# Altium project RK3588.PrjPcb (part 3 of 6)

## Sheet LAN9696.SchDoc
size A2; SheetNumber: 7; SheetTotal: 22
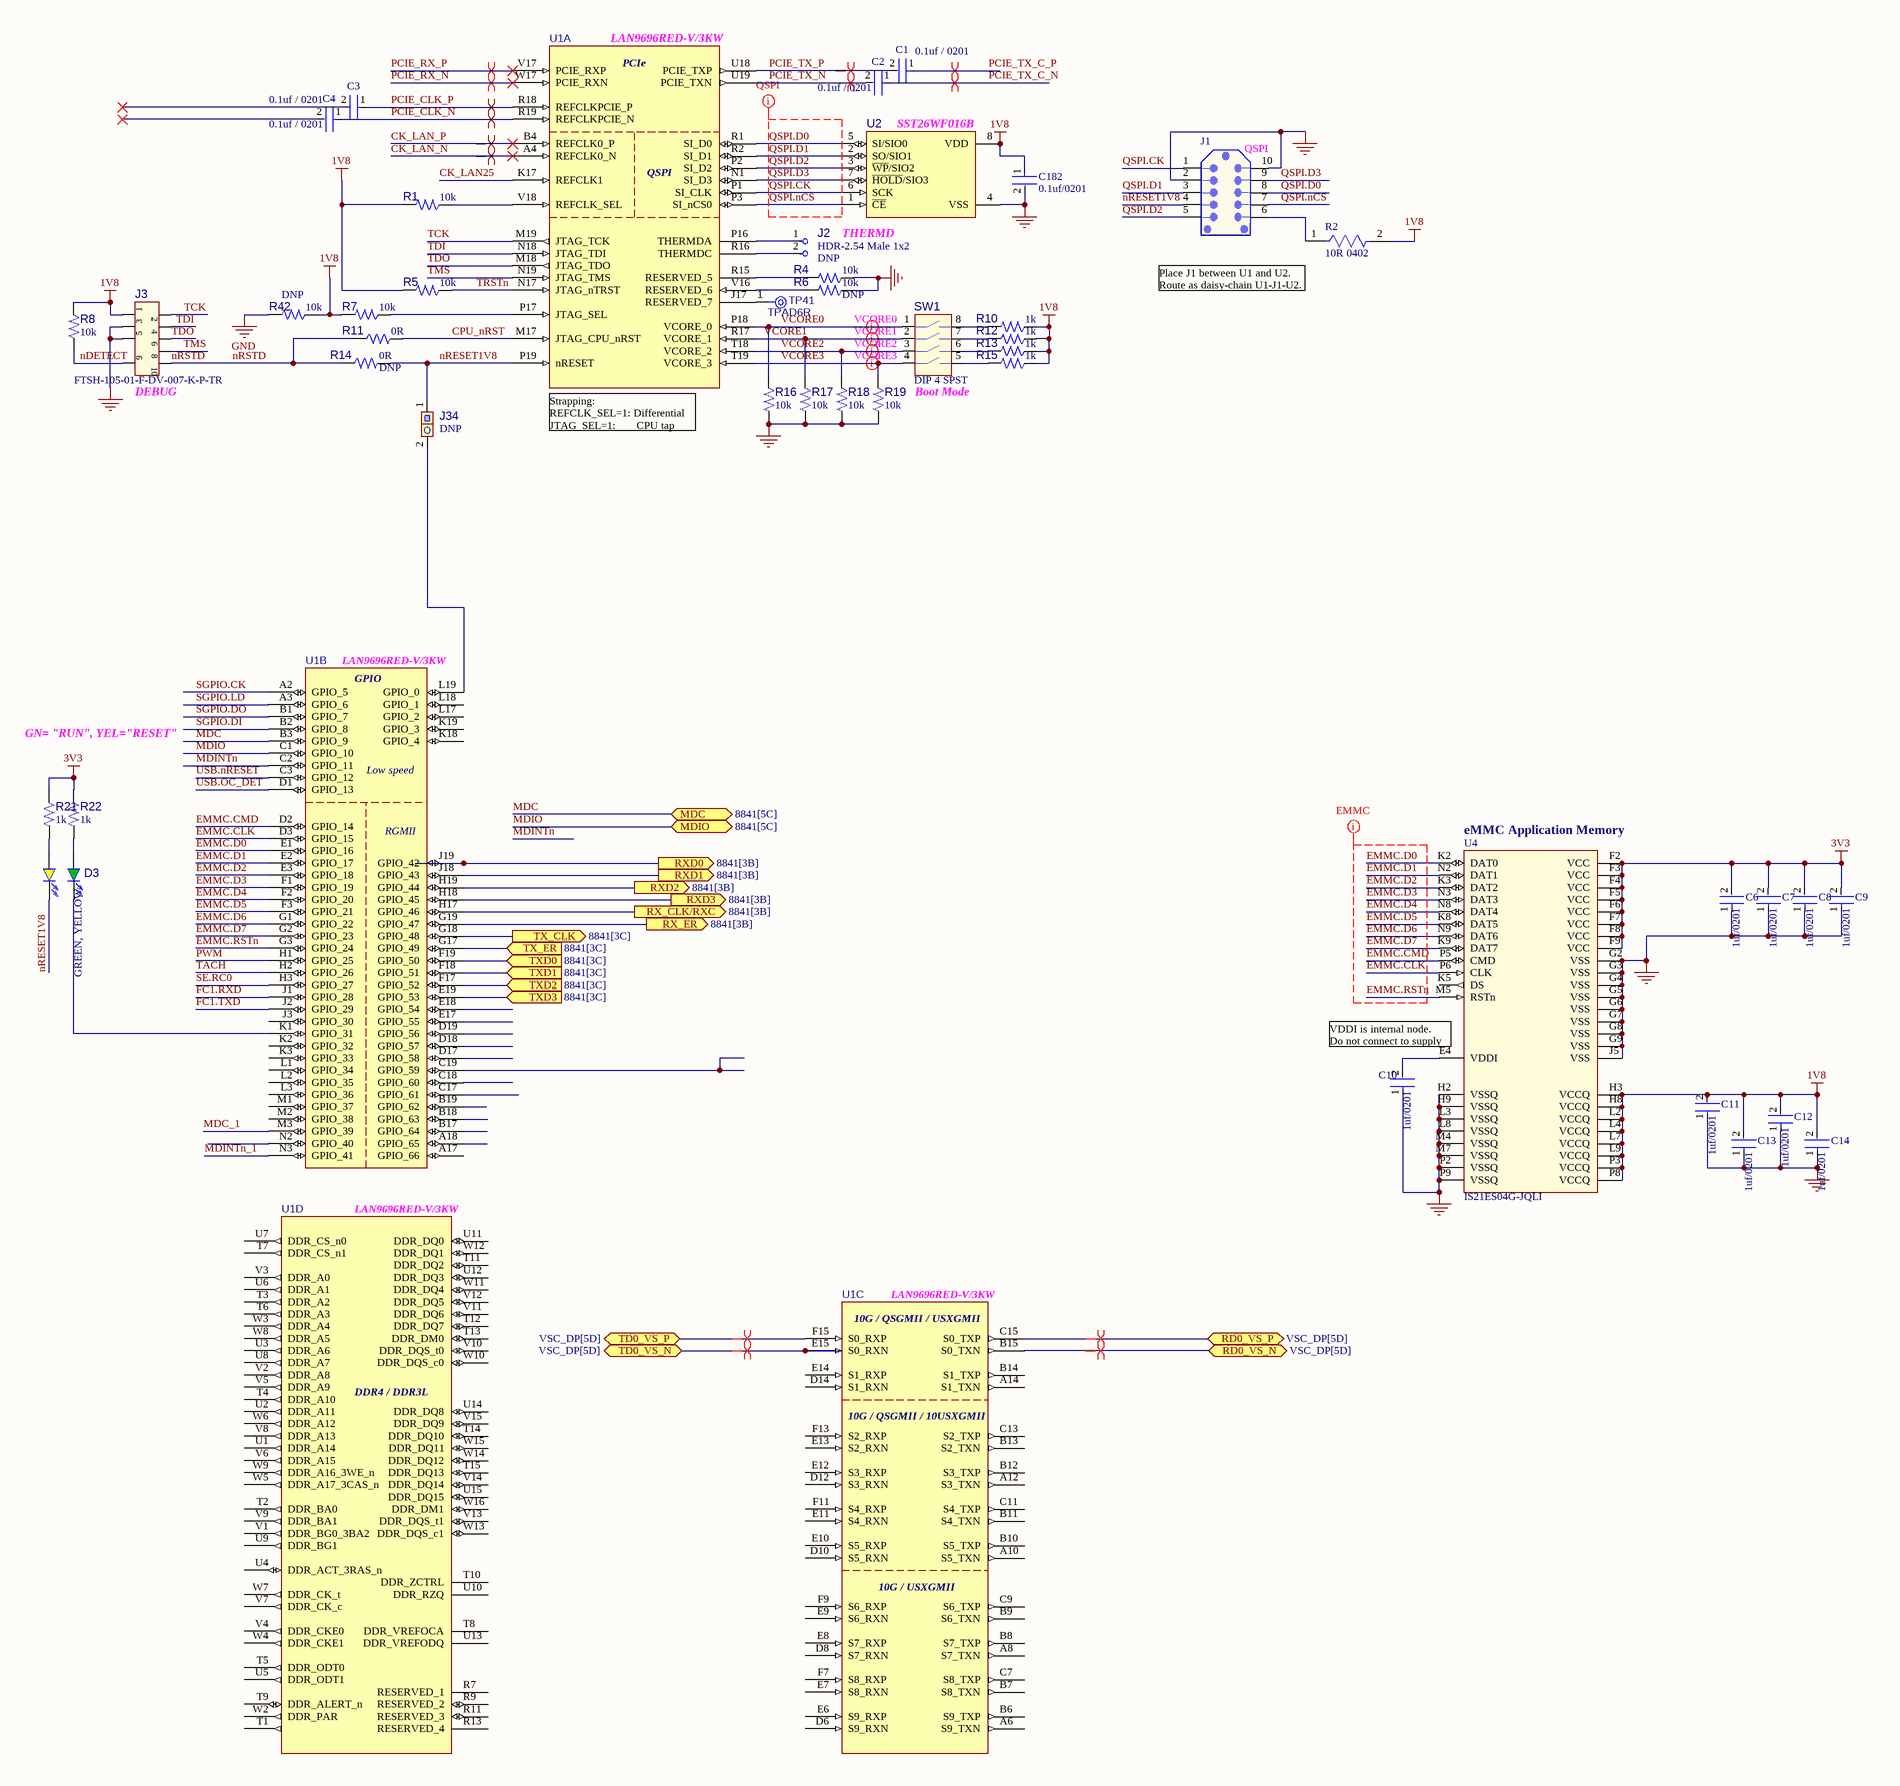
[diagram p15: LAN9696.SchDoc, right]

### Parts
C1  0.1uf / 0201  [FP-CC0201-BB-MFG]
C2  0.1uf / 0201  [FP-CC0201-BB-MFG]
C3  0.1uf / 0201  [FP-CC0201-BB-MFG]
C4  0.1uf / 0201  [FP-CC0201-BB-MFG]
C6  1uf/0201  [FP-CC0201-BA-MFG]
C7  1uf/0201  [FP-CC0201-BA-MFG]
C8  1uf/0201  [FP-CC0201-BA-MFG]
C9  1uf/0201  [FP-CC0201-BA-MFG]
C10  1uf/0201  [FP-CC0201-BA-MFG]
C11  1uf/0201  [FP-CC0201-BA-MFG]
C12  1uf/0201  [FP-CC0201-BA-MFG]
C13  1uf/0201  [FP-CC0201-BA-MFG]
C14  1uf/0201  [FP-CC0201-BA-MFG]
C182  0.1uf/0201  [FP-CC0201-BB-MFG]
D3  value GREEN, YELLOW  Legend Note: GN= "RUN", YEL="RESET"  [DIO_LED_DUAL_553-0123]  (hidden comment: LED_Dual_553-0123)
J1  Legend Note: QSPI  [CON_TAG TC2050 10P NO LEGS]  (hidden comment: CON-10P-TC2050-SMT-NO-LEGS)
J2  value HDR-2.54 Male 1x2  Populated: DNP  Legend Note: THERMD  [HDR_M_2.54_1x2]  (hidden comment: Header 1x2)
J3  value FTSH-105-01-F-DV-007-K-P-TR  Legend Note: DEBUG  [HDR_M_1.27_2x5_SMD_V_SAM_FTSH-105-01-F-DV-007-K]  (hidden comment: Header 2x5 POS 7 POLARIZED)
J34  Populated: DNP  [HDR_M_2.54_1x2]  (hidden comment: Header 1x2)
R1  value 10k  [RES_C_0402]  (hidden comment: Resistor)
R2  10R 0402  [FP-RT0402-MFG]
R4  value 10k  [RES_C_0402]  (hidden comment: Resistor)
R5  value 10k  [RES_C_0402]  (hidden comment: Resistor)
R6  value 10k  Populated: DNP  [RES_C_0402]  (hidden comment: Resistor)
R7  value 10k  [RES_C_0402]  (hidden comment: Resistor)
R8  value 10k  [RES_C_0402]  (hidden comment: Resistor)
R10  value 1k  [RES_C_0402]  (hidden comment: Resistor)
R11  value 0R  [RES_C_0402]  (hidden comment: Resistor)
R12  value 1k  [RES_C_0402]  (hidden comment: Resistor)
R13  value 1k  [RES_C_0402]  (hidden comment: Resistor)
R14  value 0R  Populated: DNP  [RES_C_0402]  (hidden comment: Resistor)
R15  value 1k  [RES_C_0402]  (hidden comment: Resistor)
R16  value 10k  [RES_C_0402]  (hidden comment: Resistor)
R17  value 10k  [RES_C_0402]  (hidden comment: Resistor)
R18  value 10k  [RES_C_0402]  (hidden comment: Resistor)
R19  value 10k  [RES_C_0402]  (hidden comment: Resistor)
R21  value 1k  [RES_C_0402]  (hidden comment: Resistor)
R22  value 1k  [RES_C_0402]  (hidden comment: Resistor)
R42  DNP  value 10k  [RES_C_0402]
SW1  value DIP 4 SPST  Legend Note: Boot Mode  [SW_SMD_1.27MM X 4 copal]  (hidden comment: Switch DIP 4 Pos)
TP41  TPAD6R  [TP06R]  (no BOM)
U1  LAN9696RED-V/3KW  [BGA-356_P0.8_17x17x1.68]  (parts A,B,C,D of 6)
U2  Legend Note: SST26WF016B  [SOIC-8]  (hidden comment: SST26WFXXX SOIC-8)
U4  value IS21ES04G-JQLI  [FBGA-100_14x18]  (hidden comment: eMMC MLC NAND flash 200MHz)

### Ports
MDC (bidir, see 8841[5C]), MDIO (bidir, see 8841[5C]), RD0_VS_N (bidir, see VSC_DP[5D]), RD0_VS_P (bidir, see VSC_DP[5D]), RX_CLK/RXC (out, see 8841[3B]), RX_ER (out, see 8841[3B]), RXD0 (out, see 8841[3B]), RXD1 (out, see 8841[3B]), RXD2 (out, see 8841[3B]), RXD3 (out, see 8841[3B]), TD0_VS_N (bidir, see VSC_DP[5D]), TD0_VS_P (bidir, see VSC_DP[5D]), TX_CLK (out, see 8841[3C]), TX_ER (in, see 8841[3C]), TXD0 (in, see 8841[3C]), TXD1 (in, see 8841[3C]), TXD2 (in, see 8841[3C]), TXD3 (in, see 8841[3C])

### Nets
1V8: C11.2 C12.2 C13.2 C14.2 C182.1 J3.1 R1.2 R2.2 R5.2 R7.2 R8.2 R10.1 R12.1 R13.1 R15.1 R42.1 U2.8(VDD) U4.H3(VCCQ) U4.H8(VCCQ) U4.L2(VCCQ) U4.L4(VCCQ) U4.L7(VCCQ) U4.L9(VCCQ) U4.P3(VCCQ) U4.P8(VCCQ)
3V3: C6.2 C7.2 C8.2 C9.2 R21.1 R22.1 U4.F2(VCC) U4.F3(VCC) U4.F4(VCC) U4.F5(VCC) U4.F6(VCC) U4.F7(VCC) U4.F8(VCC) U4.F9(VCC)
GND: C6.1 C7.1 C8.1 C9.1 C10.1 C11.1 C12.1 C13.1 C14.1 C182.2 J1.2 J1.10 J3.3 J3.5 R4.1 R6.1 R16.1 R17.1 R18.1 R19.1 R42.2 U2.4(VSS) U4.G2(VSS) U4.G3(VSS) U4.G4(VSS) U4.G5(VSS) U4.G6(VSS) U4.G7(VSS) U4.G8(VSS) U4.G9(VSS) U4.H2(VSSQ) U4.H9(VSSQ) U4.J5(VSS) U4.L3(VSSQ) U4.L8(VSSQ) U4.M4(VSSQ) U4.M7(VSSQ) U4.P2(VSSQ) U4.P9(VSSQ)
CK_LAN25: U1.K17(REFCLK1)
CK_LAN_N: U1.A4(REFCLK0_N)
CK_LAN_P: U1.B4(REFCLK0_P)
CLK125EN: U1.G19(GPIO_47) ; port RX_ER
CPU_nRST: R11.2 U1.M17(JTAG_CPU_nRST)
EMMC.CLK: U1.D3(GPIO_15) U4.P6(CLK)
EMMC.CMD: U1.D2(GPIO_14) U4.P5(CMD)
EMMC.D0: U1.E1(GPIO_16) U4.K2(DAT0)
EMMC.D1: U1.E2(GPIO_17) U4.N2(DAT1)
EMMC.D2: U1.E3(GPIO_18) U4.K3(DAT2)
EMMC.D3: U1.F1(GPIO_19) U4.N3(DAT3)
EMMC.D4: U1.F2(GPIO_20) U4.N8(DAT4)
EMMC.D5: U1.F3(GPIO_21) U4.K8(DAT5)
EMMC.D6: U1.G1(GPIO_22) U4.N9(DAT6)
EMMC.D7: U1.G2(GPIO_23) U4.K9(DAT7)
EMMC.RSTn: U1.G3(GPIO_24) U4.M5(RSTn)
FC1.RXD: U1.J1(GPIO_28)
FC1.TXD: U1.J2(GPIO_29)
MDC: U1.B3(GPIO_9) ; port MDC
MDC_1: U1.M3(GPIO_39)
MDINTn: U1.C2(GPIO_11)
MDINTn_1: U1.N3(GPIO_41)
MDIO: U1.C1(GPIO_10) ; port MDIO
MODE0: U1.J19(GPIO_42) ; port RXD0
MODE1: U1.J18(GPIO_43) ; port RXD1
MODE2: U1.H19(GPIO_44) ; port RXD2
MODE3: U1.H18(GPIO_45) ; port RXD3
MODE4: U1.H17(GPIO_46) ; port RX_CLK/RXC
nDETECT: J3.9 R8.1
nRESET1V8: D3.1 J1.4 J34.1 R14.2 U1.P19(nRESET)
nRSTD: J3.10 R11.1 R14.1
PCIE_CLK_N: C4.1 U1.R19(REFCLKPCIE_N)
PCIE_CLK_P: C3.1 U1.R18(REFCLKPCIE_P)
PCIE_RX_N: U1.W17(PCIE_RXN)
PCIE_RX_P: U1.V17(PCIE_RXP)
PCIE_TX_C_N: C2.1
PCIE_TX_C_P: C1.1
PCIE_TX_N: C2.2 U1.U19(PCIE_TXN)
PCIE_TX_P: C1.2 U1.U18(PCIE_TXP)
PWM: U1.H1(GPIO_25)
QSPI.CK: J1.1 U1.P1(SI_CLK) U2.6(SCK)
QSPI.D0: J1.8 U1.R1(SI_D0) U2.5(SI/SIO0)
QSPI.D1: J1.3 U1.R2(SI_D1) U2.2(SO/SIO1)
QSPI.D2: J1.5 U1.P2(SI_D2) U2.3(~{WP}/SIO2)
QSPI.D3: J1.9 U1.N1(SI_D3) U2.7(~{HOLD}/SIO3)
QSPI.nCS: J1.7 U1.P3(SI_nCS0) U2.1(~{CE})
RD0_VS_N: U1.B15(S0_TXN) ; port RD0_VS_N
RD0_VS_P: U1.C15(S0_TXP) ; port RD0_VS_P
SE.RC0: U1.H3(GPIO_27)
SGPIO.CK: U1.A2(GPIO_5)
SGPIO.DI: U1.B2(GPIO_8)
SGPIO.DO: U1.B1(GPIO_7)
SGPIO.LD: U1.A3(GPIO_6)
TACH: U1.H2(GPIO_26)
TCK: J3.2 U1.M19(JTAG_TCK)
TD0_VS_N: U1.E15(S0_RXN) ; port TD0_VS_N
TD0_VS_P: U1.F15(S0_RXP) ; port TD0_VS_P
TDI: J3.4 U1.N18(JTAG_TDI)
TDO: J3.6 U1.M18(JTAG_TDO)
TMS: J3.8 U1.N19(JTAG_TMS)
TRSTn: R5.1 U1.N17(JTAG_nTRST)
TX_CLK: U1.G18(GPIO_48) ; port TX_CLK
TX_ER: U1.G17(GPIO_49) ; port TX_ER
TXD0: U1.F19(GPIO_50) ; port TXD0
TXD1: U1.F18(GPIO_51) ; port TXD1
TXD2: U1.F17(GPIO_52) ; port TXD2
TXD3: U1.E19(GPIO_53) ; port TXD3
USB.nRESET: U1.C3(GPIO_12)
USB.OC_DET: U1.D1(GPIO_13)
VCORE0: R16.2 SW1.1 U1.P18(VCORE_0)
VCORE1: R17.2 SW1.2 U1.R17(VCORE_1)
VCORE2: R18.2 SW1.3 U1.T18(VCORE_2)
VCORE3: R19.2 SW1.4 U1.T19(VCORE_3)
NetC10_2: C10.2 U4.E4(VDDI)
NetD3_2: D3.2 R21.2
NetD3_3: D3.3 U1.K1(GPIO_31)
NetD3_4: D3.4 R22.2
NetJ1_6: J1.6 R2.1
NetJ2_1: J2.1 U1.P16(THERMDA)
NetJ2_2: J2.2 U1.R16(THERMDC)
NetJ34_2: J34.2 U1.L19(GPIO_0)
NetR1_1: R1.1 U1.V18(REFCLK_SEL)
NetR4_2: R4.2 U1.R15(RESERVED_5)
NetR6_2: R6.2 U1.V16(RESERVED_6)
NetR7_1: R7.1 U1.P17(JTAG_SEL)
NetR10_2: R10.2 SW1.8
NetR12_2: R12.2 SW1.7
NetR13_2: R13.2 SW1.6
NetR15_2: R15.2 SW1.5
NetTP41_1: TP41.1(TP) U1.J17(RESERVED_7)

Not connected (* = marked no-connect by the designer): C3 2*; C4 2*; U1 A6(S9_TXN) A8(S7_TXN) A10(S5_TXN) A12(S3_TXN) A14(S1_TXN) A17(GPIO_66) A18(GPIO_65) B6(S9_TXP) B7(S8_TXN) B8(S7_TXP) B9(S6_TXN) B10(S5_TXP) B11(S4_TXN) B12(S3_TXP) B13(S2_TXN) B14(S1_TXP) B17(GPIO_64) B18(GPIO_63) B19(GPIO_62) C7(S8_TXP) C9(S6_TXP) C11(S4_TXP) C13(S2_TXP) C17(GPIO_61) C18(GPIO_60) C19(GPIO_59) D6(S9_RXN) D8(S7_RXN) D10(S5_RXN) D12(S3_RXN) D14(S1_RXN) D17(GPIO_58) D18(GPIO_57) D19(GPIO_56) E6(S9_RXP) E7(S8_RXN) E8(S7_RXP) E9(S6_RXN) E10(S5_RXP) E11(S4_RXN) E12(S3_RXP) E13(S2_RXN) E14(S1_RXP) E17(GPIO_55) E18(GPIO_54) F7(S8_RXP) F9(S6_RXP) F11(S4_RXP) F13(S2_RXP) J3(GPIO_30) K2(GPIO_32) K3(GPIO_33) K18(GPIO_4) K19(GPIO_3) L1(GPIO_34) L2(GPIO_35) L3(GPIO_36) L17(GPIO_2) L18(GPIO_1) M1(GPIO_37) M2(GPIO_38) N2(GPIO_40) R7(RESERVED_1) R9(RESERVED_2) R11(RESERVED_3) R13(RESERVED_4) T1 T2(DDR_BA0) T3(DDR_A2) T4(DDR_A10) T5(DDR_ODT0) T6(DDR_A3) T7(DDR_CS_n1) T8(DDR_VREFOCA) T9(DDR_ALERT_n) T10(DDR_ZCTRL) T11(DDR_DQ2) T12(DDR_DQ7) T13(DDR_DM0) T14(DDR_DQ10) T15(DDR_DQ13) U1(DDR_A14) U2(DDR_A11) U3(DDR_A6) U4(DDR_ACT_3RAS_n) U5(DDR_ODT1) U6(DDR_A1) U7(DDR_CS_n0) U8(DDR_A7) U9(DDR_BG1) U10(DDR_RZQ) U11(DDR_DQ0) U12(DDR_DQ3) U13(DDR_VREFODQ) U14(DDR_DQ8) U15(DDR_DQ15) V1(DDR_BG0_3BA2) V2(DDR_A8) V3(DDR_A0) V4(DDR_CKE0) V5(DDR_A9) V6(DDR_A15) V7(DDR_CK_c) V8(DDR_A13) V9(DDR_BA1) V10(DDR_DQS_t0) V11(DDR_DQ6) V12(DDR_DQ5) V13(DDR_DQS_t1) V14(DDR_DQ14) V15(DDR_DQ9) W2(DDR_PAR) W3(DDR_A4) W4(DDR_CKE1) W5(DDR_A17_3CAS_n) W6(DDR_A12) W7(DDR_CK_t) W8(DDR_A5) W9(DDR_A16_3WE_n) W10(DDR_DQS_c0) W11(DDR_DQ4) W12(DDR_DQ1) W13(DDR_DQS_c1) W14(DDR_DQ12) W15(DDR_DQ11) W16(DDR_DM1); U4 K5(DS)

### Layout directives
rule Impedance Constraint [Min = 47.00    Max = 53.00    ]; net class QSPI; rule Routing Topology [Topology - Daisy-Simple]; rule Matched Net Lengths [Tolerance = 100mil]: QSPI.CK, QSPI.D0, QSPI.D1, QSPI.D2, QSPI.D3, QSPI.nCS
Legend Note: VCORE3: VCORE3
Legend Note: VCORE2: VCORE2
Legend Note: VCORE1: VCORE1
Legend Note: VCORE0: VCORE0
differential pair; rule Impedance Constraint [Min = 95.00    Max = 105.0    ]; rule Maximum Via Count Constraint [Max Count = 0]; net class HiSpeed; differential pair class PCIe; rule Matched Net Lengths [Tolerance = 5mil]: PCIE_RX_N, PCIE_RX_P, PCIE_TX_C_N, PCIE_TX_C_P
differential pair; rule Impedance Constraint [Min = 95.00    Max = 105.0    ]; rule Maximum Via Count Constraint [Max Count = 2]; differential pair class Clock; net class HiSpeed; rule Matched Net Lengths [Tolerance = 40mil]: CK_LAN_N, CK_LAN_P, PCIE_CLK_N, PCIE_CLK_P
differential pair; rule Impedance Constraint [Min = 95.00    Max = 105.0    ]; rule Maximum Via Count Constraint [Max Count = 0]; net class HiSpeed; differential pair class PCIe: PCIE_TX_N, PCIE_TX_P
rule Impedance Constraint [Min = 47.00    Max = 53.00    ]; net class EMMC_9696; rule Routing Topology [Topology - Daisy-Simple]; rule Matched Net Lengths [Tolerance = 100mil]: EMMC.CLK, EMMC.CMD, EMMC.D0, EMMC.D1, EMMC.D2, EMMC.D3, EMMC.D4, EMMC.D5, EMMC.D6, EMMC.D7, EMMC.RSTn
differential pair; net class 100Ohm: RD0_VS_N, RD0_VS_P, TD0_VS_N, TD0_VS_P

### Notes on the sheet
- Place J1 between U1 and U2.
  Route as daisy-chain U1-J1-U2.
- (near U1) Strapping:
  REFCLK_SEL=1: Differential
  JTAG_SEL=1:       CPU tap
- (near U4) eMMC Application Memory
- (near U4) VDDI is internal node.
  Do not connect to supply

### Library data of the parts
C1-C4 C182 = CMP-03422-001280-2: CAP CER 0.1UF 25V X5R 0201
C6-C14 = CMP-03422-000660-2: 1uF 6.3V X5R ±20% 0201 Multilayer Ceramic Capacitors MLCC - SMD/SMT ROHS; Manufacturer: Yageo; Manufacturer Part Number: CC0201MRX5R5BB105; Tolerance: 0.2; Temperature Coefficient: 15%; MN: CL03A105MQ3CSNH
D3 = DIODE1400: Manufacturer 1: Dialight; Manufacturer Part Number 1: 5530123F; Description_: DIO LED BI GREEN, YELLOW 2.0V 10mA TH 553-0XXX; Dev Tools Status: Design; Type: LED Bicolor; Forward Current: 10mA; Owner: Sam Charles; Populated: YES; Restricted Sourcing: No
J1 = CON1734: CON TAG 10P TC2050 SMT; Manufacturer 1: Tag-Connect LLC; Manufacturer Part Number 1: TC2050-IDC-NL; Dev Tools Status: Design; Owner: Jesus Aviles; Populated: DNP; Restricted Sourcing: No
J2 = CON1108: Manufacturer 1: FCI; Manufacturer Part Number 1: 68000-202HLF; Manufacturer 10: Shanghai NS-TECH; Manufacturer Part Number 10: NS-201-SH0100-1*2; Description_: CON HDR-2.54 Male 1x2 Gold 5.84MH TH VERT; Dev Tools Status: Production; Owner: Bogdan P (M91398); Restricted Sourcing: No
J3 = CON2256: Manufacturer 1: Samtec Inc.; Description_: CON HDR-1.27 MALE 2x5 Missing Pin 7 Polarized SMD VERT; Dev Tools Status: Production; Owner: Manikandan Balakrishnan; Populated: YES; Current: 3.4A per Contact; Restricted Sourcing: No
J34 = CON1108: Manufacturer 1: FCI; Manufacturer Part Number 1: 68000-202HLF; Manufacturer 10: Shanghai NS-TECH; Manufacturer Part Number 10: NS-201-SH0100-1*2; Value: HDR-2.54 Male 1x2; Description_: CON HDR-2.54 Male 1x2 Gold 5.84MH TH VERT; Dev Tools Status: Production; Owner: Bogdan P (M91398); Restricted Sourcing: No
R1 R4 R5 R7 R8 R16-R19 R42 = RSMT1019: Manufacturer 1: Panasonic; Manufacturer Part Number 1: ERJ-2RKF1002X; Tolerance: 1%; Description_: RES TKF 10k 1% 1/10W SMD 0402; Dev Tools Status: Production; Temperature Coeffcient: 100ppm/C; Power: 1/10W; Populated: Yes; Voltage: 50V; Owner: Brent Lanphear
R2 = CMP-2002-02548-2: RES SMD 10 OHM 1% 1/16W 0402; Manufacturer Part Number: RT0402FRE0710RL; Manufacturer: Yageo; Resistance: 10Ω; Voltage Rating: 50V; Tolerance: 0.01; Power Rating: 0.063W; Temperature Coefficient: 50 ppm/°C; Value: 10Ω
R6 = RSMT1019: Manufacturer 1: Panasonic; Manufacturer Part Number 1: ERJ-2RKF1002X; Tolerance: 1%; Description_: RES TKF 10k 1% 1/10W SMD 0402; Dev Tools Status: Production; Temperature Coeffcient: 100ppm/C; Power: 1/10W; Voltage: 50V; Owner: Brent Lanphear
R10 R12 R13 R15 R21 R22 = RES1022: Manufacturer 1: Panasonic; Manufacturer Part Number 1: ERJ-2RKF1001X; Tolerance: 1%; Description_: RES TKF 1k 1% 1/10W SMD 0402; Dev Tools Status: Production; Voltage: 50V; Power: 1/10W; Populated: YES; Owner: Tad Ahlvers; Temperature Coefficient: 100ppm/C
R11 = RSMT1040: Manufacturer 1: Yageo; Manufacturer Part Number 1: RC0402JR-070RL; Description_: RES TKF 0R 1/16W SMD 0402; Dev Tools Status: Production; Populated: Yes; Power: 1/16W; Owner: Sompoch Loboonlert
R14 = RSMT1040: Manufacturer 1: Yageo; Manufacturer Part Number 1: RC0402JR-070RL; Description_: RES TKF 0R 1/16W SMD 0402; Dev Tools Status: Production; Power: 1/16W; Owner: Sompoch Loboonlert
SW1 = SWITCH1051: Switch DIP; Manufacturer 1: Copal Electronics; Manufacturer Part Number 1: CHS-04TB; Description_: SWITCH DIP 4-POS SLIDE SMD 6V; Dev Tools Status: Production; Populated: YES
TP41 = CMP-00028-00002-2: 0.6mm round
U1 = MIC9729: Manufacturer 1: Microchip Technology; Description_: MCHP INTERFACE Industrial ETH SWITCH LAN9694 BGA356; Symbol: LAN969X BGA-356; Dev Tools Status: Design; Owner: Manikandan Balakrishnan; Populated: YES; Restricted Sourcing: No
U2 = MIC9680: Manufacturer 1: Microchip Technology; Manufacturer Part Number 1: SST26WF016BT-104I/SN; Value: SST26WF016; Description_: MCHP MEMORY SERIAL FLASH 16M 104MHz SST26WF016 SOIC-8; Dev Tools Status: Design; Owner: Sam Charles; Populated: YES; Restricted Sourcing: No
U4 = IC1641: Manufacturer 1: Flexxon; Manufacturer Part Number 1: FEMC004GTTE7-T13-17; MCHP-ID: IC1641; Description_: IC MEMORY IS21ES04G 32Gb eMMC FBGA-100; Dev Tools Status: Production; Vin: 3.3V; Owner: Ilie Galan; Populated: YES; Restricted Sourcing: No

## Sheet LAN9696_Supply.SchDoc
size A3; SheetNumber: 8; SheetTotal: 22
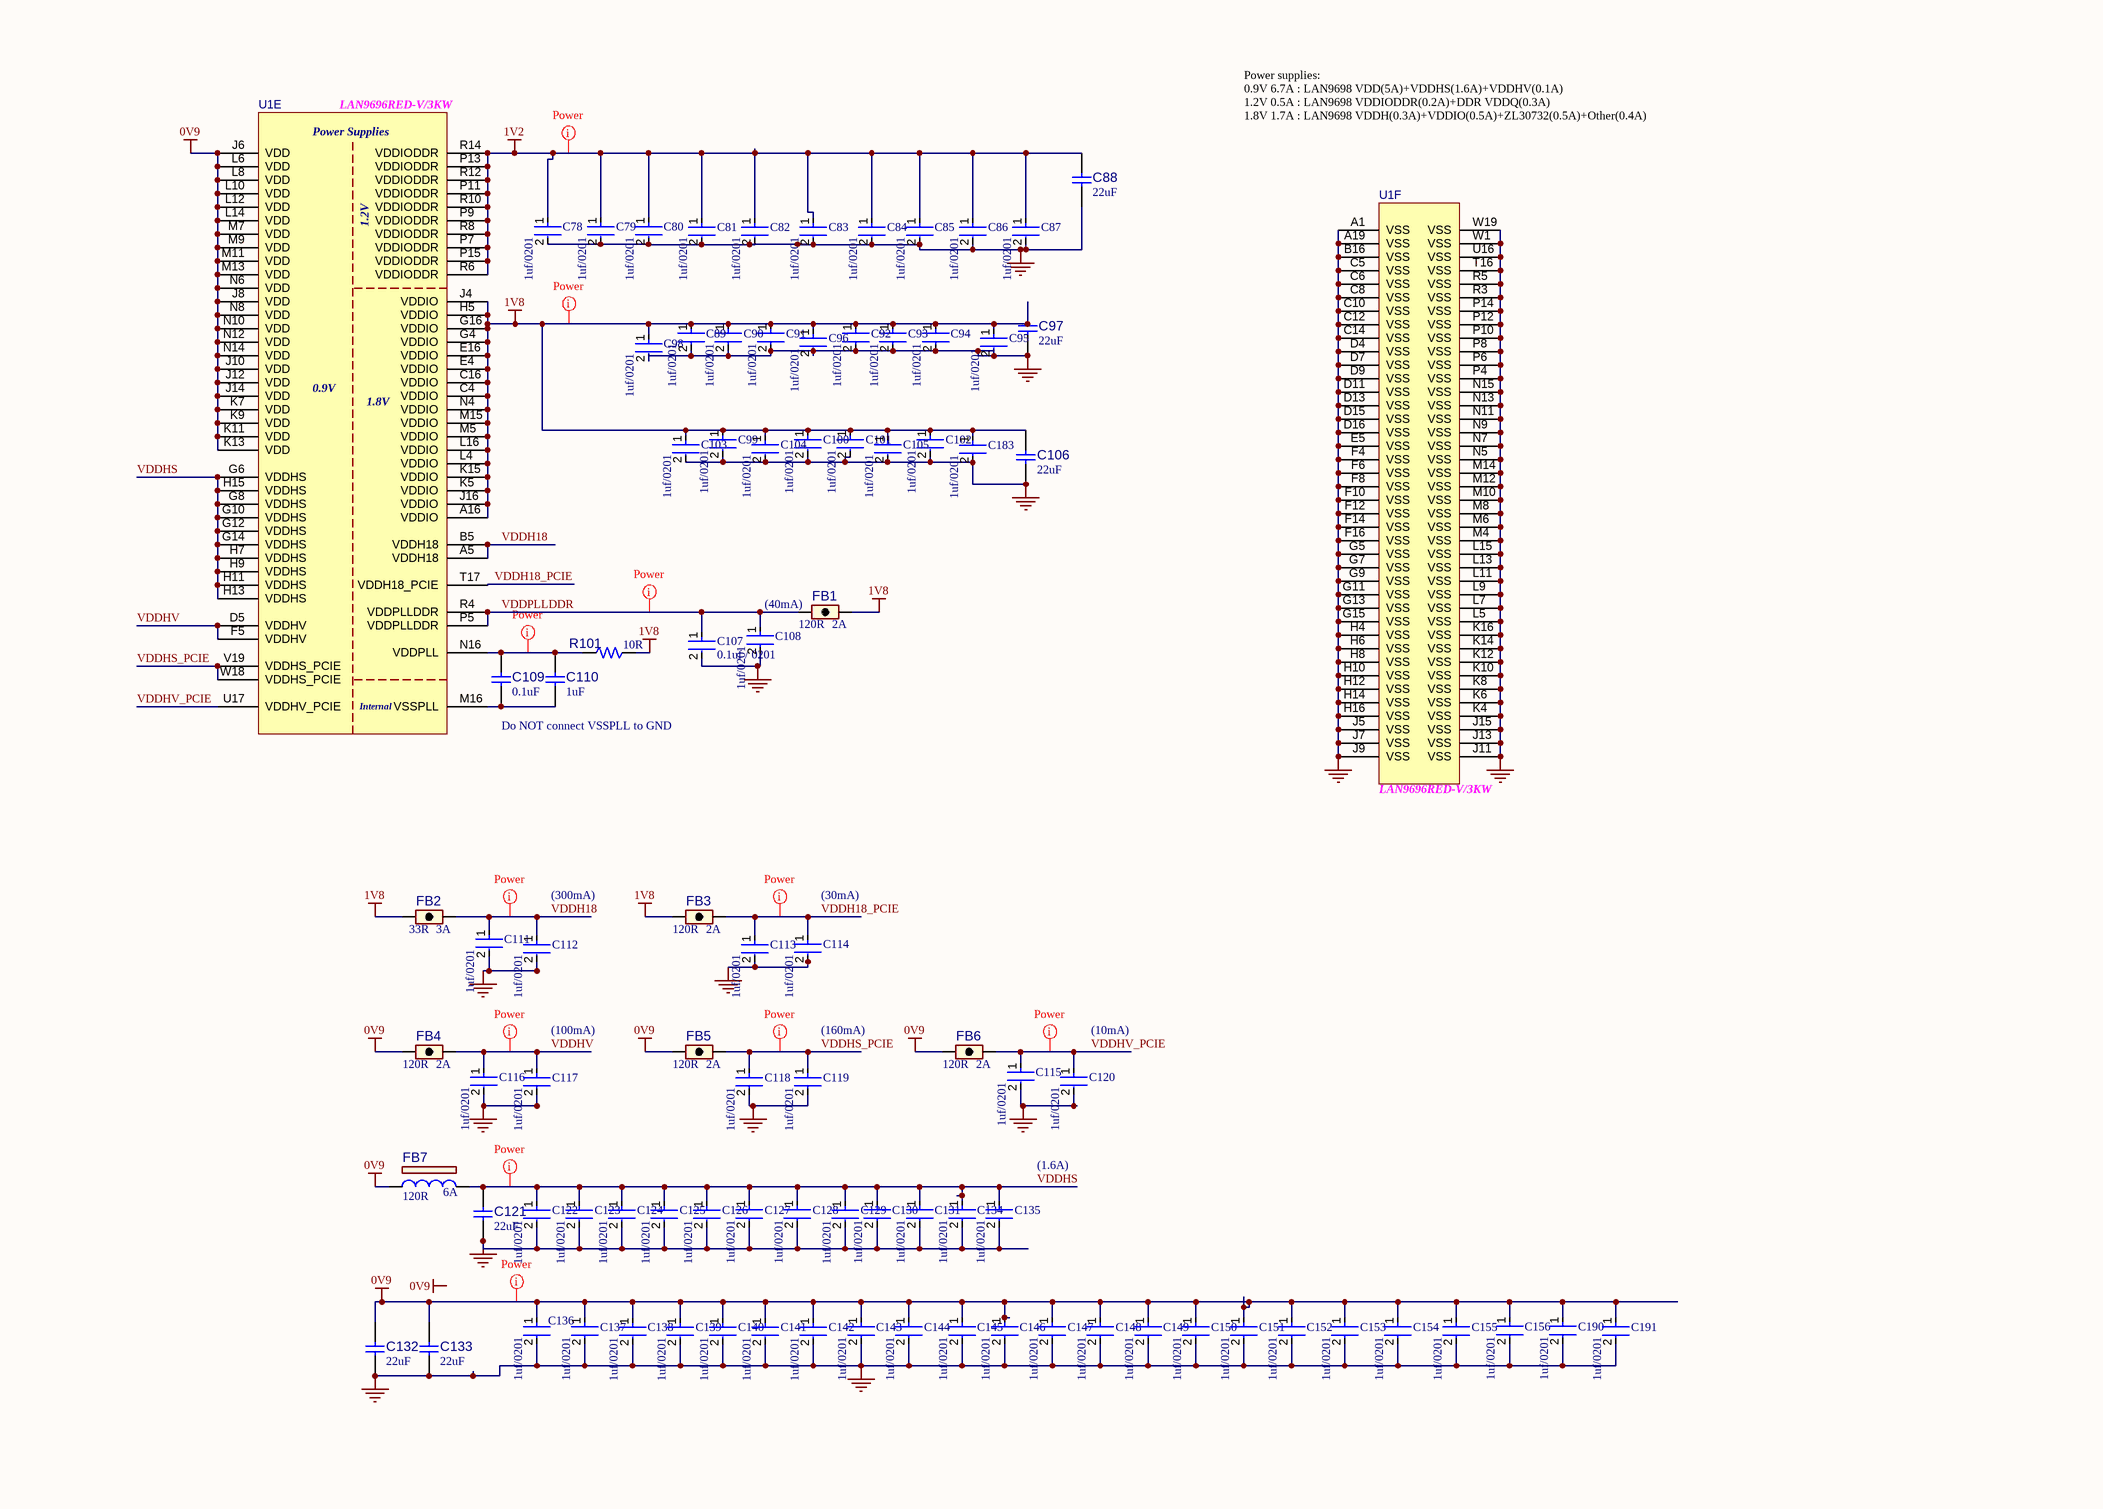
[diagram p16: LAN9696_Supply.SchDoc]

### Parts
C78  1uf/0201  [FP-CC0201-BA-MFG]
C79  1uf/0201  [FP-CC0201-BA-MFG]
C80  1uf/0201  [FP-CC0201-BA-MFG]
C81  1uf/0201  [FP-CC0201-BA-MFG]
C82  1uf/0201  [FP-CC0201-BA-MFG]
C83  1uf/0201  [FP-CC0201-BA-MFG]
C84  1uf/0201  [FP-CC0201-BA-MFG]
C85  1uf/0201  [FP-CC0201-BA-MFG]
C86  1uf/0201  [FP-CC0201-BA-MFG]
C87  1uf/0201  [FP-CC0201-BA-MFG]
C88  value 22uF  [CAP_C_0603]  (hidden comment: Capacitor NP)
C89  1uf/0201  [FP-CC0201-BA-MFG]
C90  1uf/0201  [FP-CC0201-BA-MFG]
C91  1uf/0201  [FP-CC0201-BA-MFG]
C92  1uf/0201  [FP-CC0201-BA-MFG]
C93  1uf/0201  [FP-CC0201-BA-MFG]
C94  1uf/0201  [FP-CC0201-BA-MFG]
C95  1uf/0201  [FP-CC0201-BA-MFG]
C96  1uf/0201  [FP-CC0201-BA-MFG]
C97  value 22uF  [CAP_C_0603]  (hidden comment: Capacitor NP)
C98  1uf/0201  [FP-CC0201-BA-MFG]
C99  1uf/0201  [FP-CC0201-BA-MFG]
C100  1uf/0201  [FP-CC0201-BA-MFG]
C101  1uf/0201  [FP-CC0201-BA-MFG]
C102  1uf/0201  [FP-CC0201-BA-MFG]
C103  1uf/0201  [FP-CC0201-BA-MFG]
C104  1uf/0201  [FP-CC0201-BA-MFG]
C105  1uf/0201  [FP-CC0201-BA-MFG]
C106  value 22uF  [CAP_C_0603]  (hidden comment: Capacitor NP)
C107  0.1uf / 0201  [FP-CC0201-BB-MFG]
C108  1uf/0201  [FP-CC0201-BA-MFG]
C109  value 0.1uF  [CAP_C_0201]  (hidden comment: Capacitor NP)
C110  value 1uF  [CAP_C_0201]  (hidden comment: Capacitor NP)
C111  1uf/0201  [FP-CC0201-BA-MFG]
C112  1uf/0201  [FP-CC0201-BA-MFG]
C113  1uf/0201  [FP-CC0201-BA-MFG]
C114  1uf/0201  [FP-CC0201-BA-MFG]
C115  1uf/0201  [FP-CC0201-BA-MFG]
C116  1uf/0201  [FP-CC0201-BA-MFG]
C117  1uf/0201  [FP-CC0201-BA-MFG]
C118  1uf/0201  [FP-CC0201-BA-MFG]
C119  1uf/0201  [FP-CC0201-BA-MFG]
C120  1uf/0201  [FP-CC0201-BA-MFG]
C121  value 22uF  [CAP_C_0603]  (hidden comment: Capacitor NP)
C122  1uf/0201  [FP-CC0201-BA-MFG]
C123  1uf/0201  [FP-CC0201-BA-MFG]
C124  1uf/0201  [FP-CC0201-BA-MFG]
C125  1uf/0201  [FP-CC0201-BA-MFG]
C126  1uf/0201  [FP-CC0201-BA-MFG]
C127  1uf/0201  [FP-CC0201-BA-MFG]
C128  1uf/0201  [FP-CC0201-BA-MFG]
C129  1uf/0201  [FP-CC0201-BA-MFG]
C130  1uf/0201  [FP-CC0201-BA-MFG]
C131  1uf/0201  [FP-CC0201-BA-MFG]
C132  value 22uF  [CAP_C_0603]  (hidden comment: Capacitor NP)
C133  value 22uF  [CAP_C_0603]  (hidden comment: Capacitor NP)
C134  1uf/0201  [FP-CC0201-BA-MFG]
C135  1uf/0201  [FP-CC0201-BA-MFG]
C136  1uf/0201  [FP-CC0201-BA-MFG]
C137  1uf/0201  [FP-CC0201-BA-MFG]
C138  1uf/0201  [FP-CC0201-BA-MFG]
C139  1uf/0201  [FP-CC0201-BA-MFG]
C140  1uf/0201  [FP-CC0201-BA-MFG]
C141  1uf/0201  [FP-CC0201-BA-MFG]
C142  1uf/0201  [FP-CC0201-BA-MFG]
C143  1uf/0201  [FP-CC0201-BA-MFG]
C144  1uf/0201  [FP-CC0201-BA-MFG]
C145  1uf/0201  [FP-CC0201-BA-MFG]
C146  1uf/0201  [FP-CC0201-BA-MFG]
C147  1uf/0201  [FP-CC0201-BA-MFG]
C148  1uf/0201  [FP-CC0201-BA-MFG]
C149  1uf/0201  [FP-CC0201-BA-MFG]
C150  1uf/0201  [FP-CC0201-BA-MFG]
C151  1uf/0201  [FP-CC0201-BA-MFG]
C152  1uf/0201  [FP-CC0201-BA-MFG]
C153  1uf/0201  [FP-CC0201-BA-MFG]
C154  1uf/0201  [FP-CC0201-BA-MFG]
C155  1uf/0201  [FP-CC0201-BA-MFG]
C156  1uf/0201  [FP-CC0201-BA-MFG]
C183  1uf/0201  [FP-CC0201-BA-MFG]
C190  1uf/0201  [FP-CC0201-BA-MFG]
C191  1uf/0201  [FP-CC0201-BA-MFG]
FB1  value 120R  RMS Current: 2A  [IND_C_0603]  (hidden comment: Ferrite Bead)
FB2  value 33R  Saturation Current: 3A  [IND_C_0603]  (hidden comment: Ferrite Bead)
FB3  value 120R  RMS Current: 2A  [IND_C_0603]  (hidden comment: Ferrite Bead)
FB4  value 120R  RMS Current: 2A  [IND_C_0603]  (hidden comment: Ferrite Bead)
FB5  value 120R  RMS Current: 2A  [IND_C_0603]  (hidden comment: Ferrite Bead)
FB6  value 120R  RMS Current: 2A  [IND_C_0603]  (hidden comment: Ferrite Bead)
FB7  value 120R  Saturation Current: 6A  [IND_C_1206]  (hidden comment: Ferrite Bead)
R101  value 10R  [RES_C_0402]  (hidden comment: Resistor)
U1  LAN9696RED-V/3KW  [BGA-356_P0.8_17x17x1.68]  (parts E,F of 6)

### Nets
0V9: C132.2 C133.2 C136.1 C137.1 C138.1 C139.1 C140.1 C141.1 C142.1 C143.1 C144.1 C145.1 C146.1 C147.1 C148.1 C149.1 C150.1 C151.1 C152.1 C153.1 C154.1 C155.1 C156.1 C190.1 C191.1 FB4.1 FB5.1 FB6.1 FB7.1 U1.J6(VDD) U1.J8(VDD) U1.J10(VDD) U1.J12(VDD) U1.J14(VDD) U1.K7(VDD) U1.K9(VDD) U1.K11(VDD) U1.K13(VDD) U1.L6(VDD) U1.L8(VDD) U1.L10(VDD) U1.L12(VDD) U1.L14(VDD) U1.M7(VDD) U1.M9(VDD) U1.M11(VDD) U1.M13(VDD) U1.N6(VDD) U1.N8(VDD) U1.N10(VDD) U1.N12(VDD) U1.N14(VDD)
1V2: C78.1 C79.1 C80.1 C81.1 C82.1 C83.1 C84.1 C85.1 C86.1 C87.1 C88.2 U1.P7(VDDIODDR) U1.P9(VDDIODDR) U1.P11(VDDIODDR) U1.P13(VDDIODDR) U1.P15(VDDIODDR) U1.R6(VDDIODDR) U1.R8(VDDIODDR) U1.R10(VDDIODDR) U1.R12(VDDIODDR) U1.R14(VDDIODDR)
1V8: C89.1 C90.1 C91.1 C92.1 C93.1 C94.1 C95.1 C96.1 C97.2 C98.1 C99.1 C100.1 C101.1 C102.1 C103.1 C104.1 C105.1 C106.2 C183.1 FB1.2 FB2.1 FB3.1 R101.2 U1.A16(VDDIO) U1.C4(VDDIO) U1.C16(VDDIO) U1.E4(VDDIO) U1.E16(VDDIO) U1.G4(VDDIO) U1.G16(VDDIO) U1.H5(VDDIO) U1.J4(VDDIO) U1.J16(VDDIO) U1.K5(VDDIO) U1.K15(VDDIO) U1.L4(VDDIO) U1.L16(VDDIO) U1.M5(VDDIO) U1.M15(VDDIO) U1.N4(VDDIO)
GND: C78.2 C79.2 C80.2 C81.2 C82.2 C83.2 C84.2 C85.2 C86.2 C87.2 C88.1 C89.2 C90.2 C91.2 C92.2 C93.2 C94.2 C95.2 C96.2 C97.1 C98.2 C99.2 C100.2 C101.2 C102.2 C103.2 C104.2 C105.2 C106.1 C107.2 C108.2 C111.2 C112.2 C113.2 C114.2 C115.2 C116.2 C117.2 C118.2 C119.2 C120.2 C121.1 C122.2 C123.2 C124.2 C125.2 C126.2 C127.2 C128.2 C129.2 C130.2 C131.2 C132.1 C133.1 C134.2 C135.2 C136.2 C137.2 C138.2 C139.2 C140.2 C141.2 C142.2 C143.2 C144.2 C145.2 C146.2 C147.2 C148.2 C149.2 C150.2 C151.2 C152.2 C153.2 C154.2 C155.2 C156.2 C183.2 C190.2 C191.2 U1.A1(VSS) U1.A19(VSS) U1.B16(VSS) U1.C5(VSS) U1.C6(VSS) U1.C8(VSS) U1.C10(VSS) U1.C12(VSS) U1.C14(VSS) U1.D4(VSS) U1.D7(VSS) U1.D9(VSS) U1.D11(VSS) U1.D13(VSS) U1.D15(VSS) U1.D16(VSS) U1.E5(VSS) U1.F4(VSS) U1.F6(VSS) U1.F8(VSS) U1.F10(VSS) U1.F12(VSS) U1.F14(VSS) U1.F16(VSS) U1.G5(VSS) U1.G7(VSS) U1.G9(VSS) U1.G11(VSS) U1.G13(VSS) U1.G15(VSS) U1.H4(VSS) U1.H6(VSS) U1.H8(VSS) U1.H10(VSS) U1.H12(VSS) U1.H14(VSS) U1.H16(VSS) U1.J5(VSS) U1.J7(VSS) U1.J9(VSS) U1.J11(VSS) U1.J13(VSS) U1.J15(VSS) U1.K4(VSS) U1.K6(VSS) U1.K8(VSS) U1.K10(VSS) U1.K12(VSS) U1.K14(VSS) U1.K16(VSS) U1.L5(VSS) U1.L7(VSS) U1.L9(VSS) U1.L11(VSS) U1.L13(VSS) U1.L15(VSS) U1.M4(VSS) U1.M6(VSS) U1.M8(VSS) U1.M10(VSS) U1.M12(VSS) U1.M14(VSS) U1.N5(VSS) U1.N7(VSS) U1.N9(VSS) U1.N11(VSS) U1.N13(VSS) U1.N15(VSS) U1.P4(VSS) U1.P6(VSS) U1.P8(VSS) U1.P10(VSS) U1.P12(VSS) U1.P14(VSS) U1.R3(VSS) U1.R5(VSS) U1.T16(VSS) U1.U16(VSS) U1.W1(VSS) U1.W19(VSS)
VDDH18: C111.1 C112.1 FB2.2 U1.A5(VDDH18) U1.B5(VDDH18)
VDDH18_PCIE: C113.1 C114.1 FB3.2 U1.T17(VDDH18_PCIE)
VDDHS: C121.2 C122.1 C123.1 C124.1 C125.1 C126.1 C127.1 C128.1 C129.1 C130.1 C131.1 C134.1 C135.1 FB7.2 U1.G6(VDDHS) U1.G8(VDDHS) U1.G10(VDDHS) U1.G12(VDDHS) U1.G14(VDDHS) U1.H7(VDDHS) U1.H9(VDDHS) U1.H11(VDDHS) U1.H13(VDDHS) U1.H15(VDDHS)
VDDHS_PCIE: C118.1 C119.1 FB5.2 U1.V19(VDDHS_PCIE) U1.W18(VDDHS_PCIE)
VDDHV: C116.1 C117.1 FB4.2 U1.D5(VDDHV) U1.F5(VDDHV)
VDDHV_PCIE: C115.1 C120.1 FB6.2 U1.U17(VDDHV_PCIE)
VDDPLLDDR: C107.1 C108.1 FB1.1 U1.P5(VDDPLLDDR) U1.R4(VDDPLLDDR)
NetC109_1: C109.1 C110.1 U1.M16(VSSPLL)
NetC109_2: C109.2 C110.2 R101.1 U1.N16(VDDPLL)

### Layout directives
net class Power: 0V9, 1V2, 1V8, NetC109_2, VDDH18, VDDH18_PCIE, VDDHS, VDDHS_PCIE, VDDHV, VDDHV_PCIE, VDDPLLDDR

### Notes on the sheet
- Power supplies:
  0.9V 6.7A : LAN9698 VDD(5A)+VDDHS(1.6A)+VDDHV(0.1A)
  1.2V 0.5A : LAN9698 VDDIODDR(0.2A)+DDR VDDQ(0.3A)
  1.8V 1.7A : LAN9698 VDDH(0.3A)+VDDIO(0.5A)+ZL30732(0.5A)+Other(0.4A)
- (near FB1) (40mA)
- VDDPLL should have 100R for 1 PLL,
  there are 5? PLLs.  ???R
- Do NOT connect VSSPLL to GND
- (near C112) (300mA)
- (near C114) (30mA)
- (near C117) (100mA)
- (near C119) (160mA)
- (near C120) (10mA)
- (1.6A)
- Labels drawn without touching a wire or pin: 0V9

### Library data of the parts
C78-C87 C89-C96 C98-C105 C108 C111-C120 C122-C131 C134-C156 C183 C190 C191 = CMP-03422-000660-2: CAP CER 1UF 6.3V X5R 0201; Manufacturer: Yageo; Manufacturer Part Number: CC0201MRX5R5BB105; Tolerance: 0.2; Material: Ceramic; Temperature Coefficient: 15%
C88 C97 C106 C121 C132 C133 = CAP1648: Manufacturer 1: TDK Corporation; Manufacturer Part Number 1: C1608X5R1A226M080AC; Voltage: 10V; Description_: CAP CER 22uF 10V 20% X5R SMD 0603; Dev Tools Status: Production; Temperature Coefficient: X5R; Type: Ceramic; Populated: YES; Tolerance: 20%; Owner: Razvan Cristescu; Restricted Sourcing: No
C107 = CMP-03422-001280-2: CAP CER 0.1UF 25V X5R 0201
C109 = CAP2712: Manufacturer 1: Murata Electronics; Manufacturer Part Number 1: GRM033R61A104KE15D; Voltage: 10V; Description_: CAP CER 0.1uF 10V 10% 0201; Dev Tools Status: Design; Tolerance: 10%; Temperature Coefficient: X5R; Type: Ceramic; Owner: Balaji Narayana; Populated: YES; Restricted Sourcing: No
C110 = CAP2679: Manufacturer 1: Murata; Manufacturer Part Number 1: GRM033R60J105MEA2D; Voltage: 6.3V; Description_: CAP CER 1uF 6.3V 20% X5R SMD 0201; Dev Tools Status: Design; Tolerance: 20%; Temperature Coefficient: X5R; Type: Ceramic; Owner: Balaji Narayana; Populated: YES; Restricted Sourcing: No
FB1 FB3-FB6 = IND1640: Manufacturer 1: TDK Corporation; Manufacturer Part Number 1: MPZ1608S121ATDH5; Description_: FERRITE 120R@100MHZ 2A SMD 0603; Dev Tools Status: Production; Owner: Sam Charles; DCR: 0.045R; Test Frequency: 100MHz; Populated: YES; Restricted Sourcing: No
FB2 = FB1007: Manufacturer 1: Murata; Manufacturer Part Number 1: BLM18PG330SN1D; MCHP-ID: FB1007; Description_: FERRITE 33R@100MHz 3A SMD 0603; Dev Tools Status: Production; Owner: Ranjana Kumari; DCR: 0.025R; Test Frequency: 100MHz; Populated: YES; Restricted Sourcing: No
FB7 = IND1986: Manufacturer 1: Murata; Manufacturer Part Number 1: BLM31KN121SZ1L; Description_: FERRITE 120R@100MHz 6A 9mOhm SMD 1206 AEC-Q200; Dev Tools Status: Design; Owner: Mihai Chivu; DCR: 0.009R; Test Frequency: 100MHz; Populated: YES; Restricted Sourcing: No
R101 = RES3010: Manufacturer 1: Vishay Dale; Manufacturer Part Number 1: CRCW040210R0FKEDC; Description_: RES TKF 10R 1% 1/16W SMD 0402; Dev Tools Status: Production; Populated: YES; Power: 1/16W; Owner: Balaji Narayana; Tolerance: 1%; Temperature Coefficient: 100ppm/C; Restricted Sourcing: No
U1 = MIC9729: as U1 on sheet LAN9696

## Sheet LAN_Supply.SchDoc
size A3; SheetNumber: 9; SheetTotal: 23
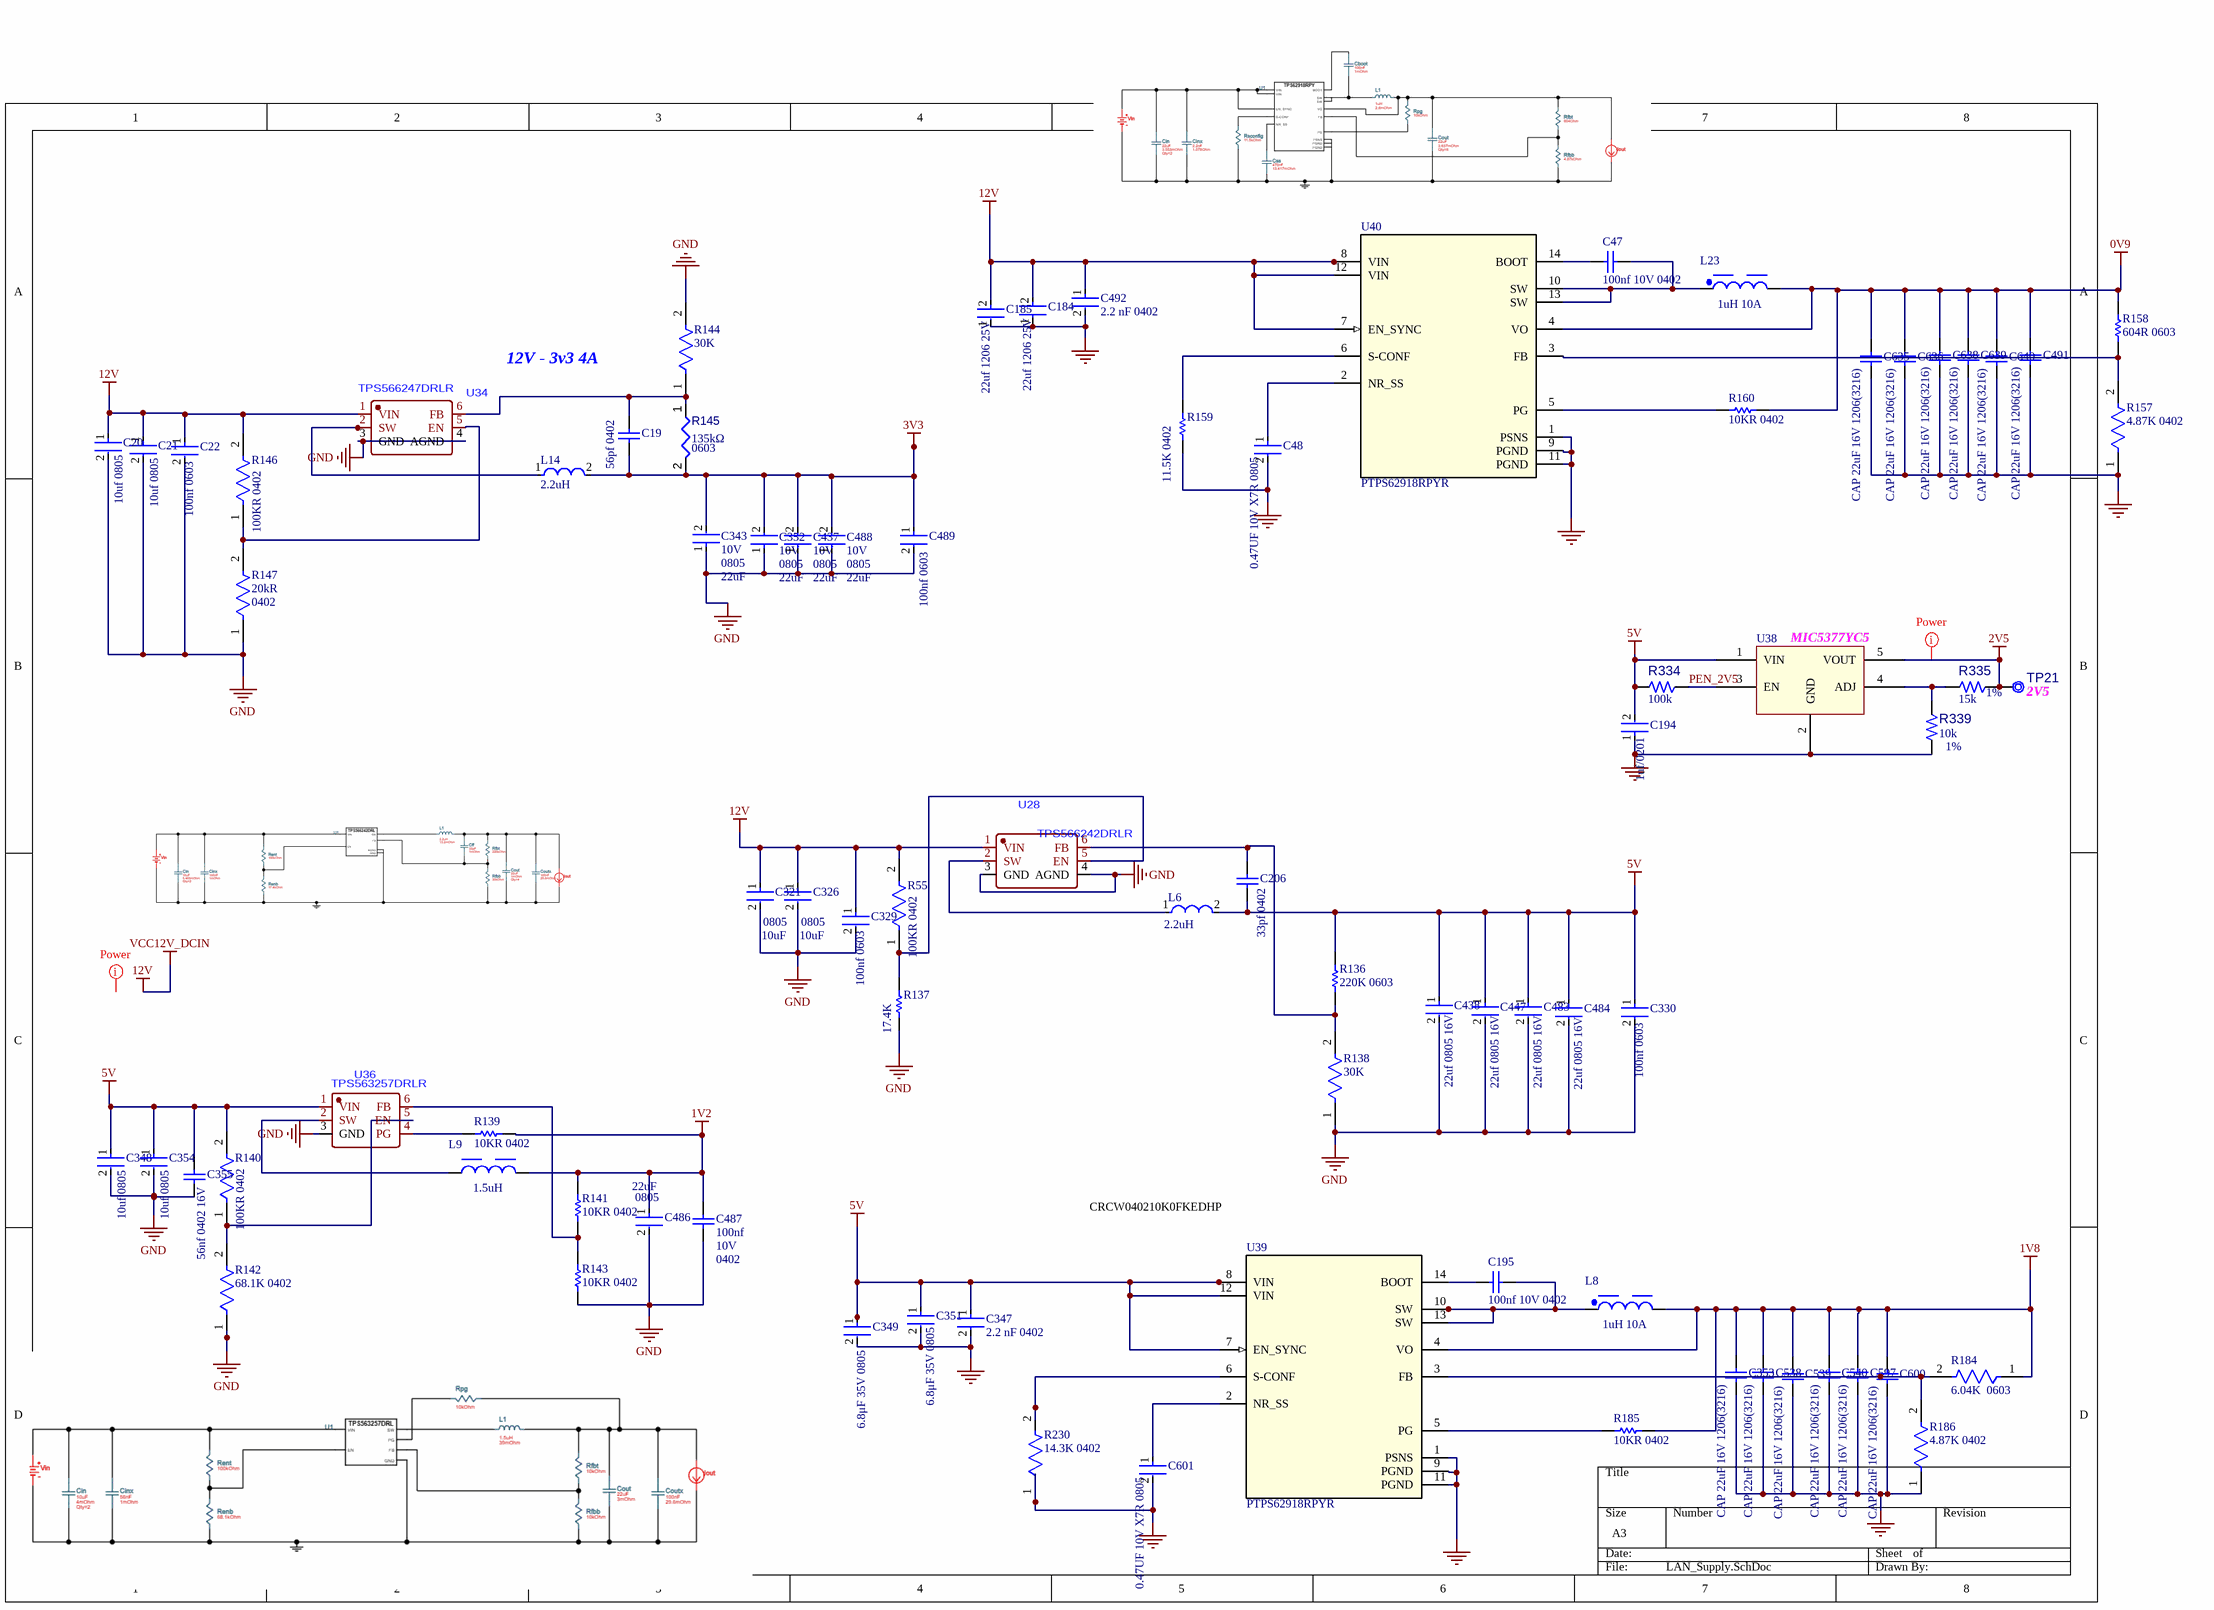
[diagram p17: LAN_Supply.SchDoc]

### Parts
C19  56pf 0402  [CAPC1005X56X25LL10T15]
C20  10uf 0805  [FP-C0805C106K3PACTU-MFG]
C21  10uf 0805  [FP-C0805C106K3PACTU-MFG]
C22  100nf 0603  [FP-GRM188-0_1-e0_2_0_5-IPC_B]
C47  100nf 10V 0402  [CAPC1005X55X25LL05T10]
C48  0.47UF 10V X7R 0805  [FP-C0805C-DN-MFG]
C184  22uf 1206 25V  [FP-GRM31C-0_3-e0_3_0_8-IPC_A]
C185  22uf 1206 25V  [FP-GRM31C-0_3-e0_3_0_8-IPC_A]
C194  1uf/0201  [FP-CC0201-BA-MFG]
C195  100nf 10V 0402  [CAPC1005X55X25LL05T10]
C206  33pf 0402  [CAPC1005X55X25ML05T10]
C321  Capacitance: 10uF  Case/Package: 0805  [FP-C0805C106K3PACTU-MFG]  (hidden comment: C0805C106K3PACTU)
C326  Capacitance: 10uF  Case/Package: 0805  [FP-C0805C106K3PACTU-MFG]  (hidden comment: C0805C106K3PACTU)
C329  100nf 0603  [FP-GRM188-0_1-e0_2_0_5-IPC_B]
C330  100nf 0603  [FP-GRM188-0_1-e0_2_0_5-IPC_B]
C343  Voltage: 10V  Case Code (Imperial): 0805  Capacitance: 22uF  [FP-GRM21B-0_2-e0_2_0_7-IPC_C]  (hidden comment: GRM21BR61A226ME44L)
C347  2.2 nF 0402  [FP-CGA2B-IPC_B]
C348  10uf 0805  [FP-C0805C106K3PACTU-MFG]
C349  6.8μF 35V 0805  [FP-C2012-125-0_2-IPC_B]
C351  6.8μF 35V 0805  [FP-C2012-125-0_2-IPC_B]
C352  Voltage: 10V  Case Code (Imperial): 0805  Capacitance: 22uF  [FP-GRM21B-0_2-e0_2_0_7-IPC_C]  (hidden comment: GRM21BR61A226ME44L)
C353  CAP 22uF 16V 1206(3216)  [CAPC1206(3216)190_L]
C354  10uf 0805  [FP-C0805C106K3PACTU-MFG]
C355  56nf 0402 16V  [CAPC1005X55X25ML05T10]
C437  Voltage: 10V  Case Code (Imperial): 0805  Capacitance: 22uF  [FP-GRM21B-0_2-e0_2_0_7-IPC_C]  (hidden comment: GRM21BR61A226ME44L)
C438  22uf 0805 16V  [FP-GRM21B-0_2-e0_2_0_7-IPC_C]
C447  22uf 0805 16V  [FP-GRM21B-0_2-e0_2_0_7-IPC_C]
C483  22uf 0805 16V  [FP-GRM21B-0_2-e0_2_0_7-IPC_C]
C484  22uf 0805 16V  [FP-GRM21B-0_2-e0_2_0_7-IPC_C]
C486  Case Code (Imperial): 0805  Capacitance: 22uF  [FP-C0805C226M8PACTU-MFG]  (hidden comment: C0805C226M8PACTU)
C487  100nf  Rated Voltage: 10V  Package Reference: 0402  [CAPC1005X55X25LL05T10]
C488  Voltage: 10V  Case Code (Imperial): 0805  Capacitance: 22uF  [FP-GRM21B-0_2-e0_2_0_7-IPC_C]  (hidden comment: GRM21BR61A226ME44L)
C489  100nf 0603  [FP-GRM188-0_1-e0_2_0_5-IPC_B]
C491  CAP 22uF 16V 1206(3216)  [CAPC1206(3216)190_L]
C492  2.2 nF 0402  [FP-CGA2B-IPC_B]
C538  CAP 22uF 16V 1206(3216)  [CAPC1206(3216)190_L]
C539  CAP 22uF 16V 1206(3216)  [CAPC1206(3216)190_L]
C540  CAP 22uF 16V 1206(3216)  [CAPC1206(3216)190_L]
C597  CAP 22uF 16V 1206(3216)  [CAPC1206(3216)190_L]
C600  CAP 22uF 16V 1206(3216)  [CAPC1206(3216)190_L]
C601  0.47UF 10V X7R 0805  [FP-C0805C-DN-MFG]
C635  CAP 22uF 16V 1206(3216)  [CAPC1206(3216)190_L]
C636  CAP 22uF 16V 1206(3216)  [CAPC1206(3216)190_L]
C638  CAP 22uF 16V 1206(3216)  [CAPC1206(3216)190_L]
C639  CAP 22uF 16V 1206(3216)  [CAPC1206(3216)190_L]
C640  CAP 22uF 16V 1206(3216)  [CAPC1206(3216)190_L]
L6  Inductance: 2.2uH  [FP-XAL5030-222MEB-MFG]  (hidden comment: XAL5030-222MEB)
L8  1uH 10A  [WE-MAPI_4020]
L9  1.5uH  [WE-MAPI_3020]
L14  2.2uH  [FP-XAL5030-222MEB-MFG]
L23  1uH 10A  [WE-MAPI_4020]
R55  100KR 0402  [FP-CRCW0402-e3-IPC_C]
R136  220K 0603  [RESC1608X55X25ML10T15]
R137  17.4K  [RESC1005X40X25LL05T05]
R138  30K  [FP-AT0603-IPC_B]
R139  10KR 0402  [RESC1005X40X25ML05T10]
R140  100KR 0402  [FP-CRCW0402-e3-IPC_C]
R141  10KR 0402  [RESC1005X40X25ML05T10]
R142  68.1K 0402  [FP-CRCW0402-e3-IPC_B]
R143  10KR 0402  [RESC1005X40X25ML05T10]
R144  30K  [FP-AT0603-IPC_B]
R145  value 135kΩ  Case/Package: 0603  [RESC0603(1608)_L]  (hidden comment: RT0603BRD07135KL)
R146  100KR 0402  [FP-CRCW0402-e3-IPC_C]
R147  Resistance: 20kR  Case/Package: 0402  [FP-CRCW0402-e3-IPC_B]  (hidden comment: CRCW040220K0FKED)
R157  4.87K 0402  [FP-CRCW0402-e3-IPC_C]
R158  604R 0603  [RESC1609X50X30ML10T20]
R159  11.5K 0402  [RESC1005X40X25NL05T05]
R160  10KR 0402  [RESC1005X40X25ML05T10]
R184  6.04K  0603  [FP-RC0603-0_55-IPC_A]
R185  10KR 0402  [RESC1005X40X25ML05T10]
R186  4.87K 0402  [FP-CRCW0402-e3-IPC_C]
R230  14.3K 0402  [FP-CRCW0402-e3-MFG]
R334  value 100k  [RES_C_0603]  (hidden comment: Resistor)
R335  value 15k  Tolerance: 1%  [RES_C_0603]  (hidden comment: Resistor)
R339  value 10k  Tolerance: 1%  [RES_C_0402]  (hidden comment: Resistor)
TP21  Legend Note: 2V5  [TP_1x0.6]  (hidden comment: Test Point No BOM)  (no BOM)
U28  TPS566242DRLR  [SOT-666-6_L1.6-W1.2-P0.50-LS1.6-BL]
U34  TPS566247DRLR  [SOT-5X3-6_W1.6-L1.2-P0.50-LS1.6-BL]
U36  TPS563257DRLR  [SOT-666-6_L1.6-W1.2-P0.50-LS1.6-BR]
U38  MIC5377YC5  [SC-70-5]
U39  PTPS62918RPYR  [RPY0014A-MFG]
U40  PTPS62918RPYR  [RPY0014A-MFG]

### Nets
0V9: C491.2 C635.2 C636.2 C638.2 C639.2 C640.2 L23.2 R158.2 R160.1 U40.4(VO)
1V2: C486.1 C487.2 L9.2 R139.1 R141.2
1V8: C353.2 C538.2 C539.2 C540.2 C597.2 C600.2 L8.2 R184.1 R185.1 U39.4(VO)
2V5: R335.2 TP21.1 U38.5(VOUT)
3V3: C19.1 C343.2 C352.2 C437.2 C488.2 C489.1 L14.2 R145.2
5V: C194.2 C206.2 C330.1 C347.1 C348.1 C349.1 C351.1 C354.1 C355.2 C438.1 C447.1 C483.1 C484.1 L6.2 R136.2 R140.2 R334.1 U36.1(VIN) U38.1(VIN) U39.7(EN_SYNC) U39.8(VIN) U39.12(VIN)
12V: C20.1 C21.1 C22.1 C184.2 C185.2 C321.1 C326.1 C329.1 C492.1 R55.2 R146.2 U28.1(VIN) U34.1(VIN) U40.7(EN_SYNC) U40.8(VIN) U40.12(VIN)  [also labelled VCC12V_DCIN]
GND: C20.2 C21.2 C22.2 C48.2 C184.1 C185.1 C194.1 C321.2 C326.2 C329.2 C330.2 C343.1 C347.2 C348.2 C349.2 C351.2 C352.1 C353.1 C354.2 C355.1 C437.1 C438.2 C447.2 C483.2 C484.2 C486.2 C487.1 C488.1 C489.2 C491.1 C492.2 C538.1 C539.1 C540.1 C597.1 C600.1 C601.2 C635.1 C636.1 C638.1 C639.1 C640.1 R137.1 R138.1 R142.1 R143.1 R144.2 R147.1 R157.1 R159.1 R186.1 R230.1 R339.2 U28.3(GND) U28.4(AGND) U34.3(GND) U34.4(AGND) U36.3(GND) U38.2(GND) U39.1(PSNS) U39.9(PGND) U39.11(PGND) U40.1(PSNS) U40.9(PGND) U40.11(PGND)
PEN_2V5: R334.2 U38.3(EN)
NetC19_2: C19.2 R144.1 R145.1 U34.6(FB)
NetC47_1: C47.1 U40.14(BOOT)
NetC47_2: C47.2 L23.1 U40.10(SW) U40.13(SW)
NetC48_1: C48.1 U40.2(NR_SS)
NetC195_1: C195.1 U39.14(BOOT)
NetC195_2: C195.2 L8.1 U39.10(SW) U39.13(SW)
NetC206_1: C206.1 R136.1 R138.2 U28.6(FB)
NetC601_1: C601.1 U39.2(NR_SS)
NetL6_1: L6.1 U28.2(SW)
NetL9_1: L9.1 U36.2(SW)
NetL14_1: L14.1 U34.2(SW)
NetR55_1: R55.1 R137.2 U28.5(EN)
NetR139_2: R139.2 U36.4(PG)
NetR140_1: R140.1 R142.2 U36.5(EN)
NetR141_1: R141.1 R143.2 U36.6(FB)
NetR146_1: R146.1 R147.2 U34.5(EN)
NetR157_2: R157.2 R158.1 U40.3(FB)
NetR159_2: R159.2 U40.6(S-CONF)
NetR160_2: R160.2 U40.5(PG)
NetR184_2: R184.2 R186.2 U39.3(FB)
NetR185_2: R185.2 U39.5(PG)
NetR230_2: R230.2 U39.6(S-CONF)
NetR335_1: R335.1 R339.1 U38.4(ADJ)

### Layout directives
net class Power: 2V5, (no net found under the mark)

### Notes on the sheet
- 12V - 3v3 4A
- CRCW040210K0FKEDHP

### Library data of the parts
C19 = CMP-2008-02504-1: 04023A560KAT2A; Manufacturer: AVX Interconnect / Elco
C20 C21 C321 C326 C348 C354 = CMP-03020-034663-1: CAP CER 10UF 25V X5R 0805; Dissipation Factor: 10%; Dielectric Material: Ceramic
C22 C329 C330 C489 = CMP-1035-02595-8: Chip Multilayer Ceramic Capacitors for General Purpose, 0603, 0.10uF, X7R, 15%, 10%, 100V
C47 C195 C487 = CMP-2000-06331-1: Chip Capacitor, 0.1 uF, +/- 10%, 10 V, -55 to 125 degC, 0402 (1005 Metric), RoHS, Tape and Reel; Manufacturer: Murata; Capacitance: 100000pF; Dielectric: X7R
C48 C601 = CMP-1036-04630-2: CAP CER 0.47UF 10V X7R 0805 / C0805C474J8RACTU; Manufacturer: KEMET; Description: C0805 0.47 μF X7R 30ppm/°C 5.00% 10 V; Value: 0.47 μF; Temperature Coefficient: 30ppm/°C; Tolerance: 0.05; Material: Ceramic
C184 C185 = CMP-06035-027412-1: Chip Multilayer Ceramic Capacitors for General Purpose, 1206, 22uF, X6S, 22%, 20%, 25V / GRM31CC81E226ME11K
C194 = CMP-03422-000660-2: as C6-C14 on sheet LAN9696
C206 = CMP-2008-04196-1: GRM1555C1E330JA01D; Manufacturer: Murata
C343 C352 C437 C488 = CMP-06035-039918-1: Chip Multilayer Ceramic Capacitors for General Purpose, 0805, 22uF, X5R, 15%, 20%, 10V / GRM21BR61A226ME44L; Dissipation Factor: 0.035%
C347 C492 = CMP-08246-001970-1: Cap Ceramic 2.2nF 50V X7R 10% Pad SMD 0402 +125°C Automotive T/R
C349 C351 = CMP-08246-006695-1: Multilayer Ceramic Capacitors 6.8μF ±10% 35V X5R SMD 0805 / C2012X5R1V685K125AC; Capacitance: 6.8uF
C353 C491 C538-C540 C597 C600 C635 C636 C638-C640 = CMP-1037-04994-1: CAP 22uF 16V -20% to +80% 1206 (3216 Metric) Thickness 1.9mm SMD; Case-Metric: 3216; Case-EIA: 1206
C355 = CMP-2008-04611-1: GRM155R71C563KA88D; Manufacturer: Murata
C438 C447 C483 C484 = CMP-06035-025383-1: Chip Multilayer Ceramic Capacitors for General Purpose, 0805, 22uF, X5R, 15%, 20%, 16V
C486 = CMP-03020-034697-1: CAP CER 22UF 10V X5R 0805; Tolerance: 20%; Dissipation Factor: 10%; Dielectric Material: Ceramic
L6 L14 = CMP-11268-000050-1: Fixed Inductors 2.2uH 20% 9.7A 14.5mOhms; DC Resistance (DCR): 14.5mR; Shielding: Shielded; Max DC Current: 9.2A; Test Frequency: 100kHz; Self Resonant Frequency: 38MHz; Core Material: Composite
L8 L23 = CMP-03913-66963829-3: Inductor Power Shielded Wirewound 1uH 20% 100KHz Metal 10.1A 0.015Ohm DCR T/R Automotive AEC-Q200; Core Material: Composite, Metal; Current Rating: 7.2A; Self Resonant Frequency: 55MHz; Inductance: 1µH; Saturation Current: 9A; DC Resistance (DCR): 12mΩ
L9 = CMP-03913-49216450-3: Fixed Ind 1.5UH 3.7A 39 Mohm SMD; Shielding: Shielded; Saturation Current: 4.5A; Inductance Tolerance: 20%; Core Material: Composite, Ferrite, Metal; Test Frequency: 100kHz; Self Resonant Frequency: 51MHz; DC Resistance (DCR): 33mΩ; Inductance: 1.5µH
R55 R140 R146 = CMP-2002-08123-3: RES Thick Film, 100kΩ, 1%, 0.063W, 100ppm/°C, 0402; Power Rating: 63mW; Voltage Rating (DC): 50V
R136 = CMP-1659-00037-1: Chip Resistor, 220 KOhm, +/- 1%, 100 mW, -55 to 155 degC, 0603 (1608 Metric), RoHS, Tape and Reel; Resistance: 0.1 Ohm; MN: RC0603FR-07220KL
R137 = CMP-2002-08248-1: CRCW040217K4FKED; Manufacturer: Vishay Dale
R138 R144 = CMP-03412-049842-1: Thin Film Chip Resistors Automotive Grade 30kΩ 1% 50ppm/°C 0603
R139 R141 R143 = CMP-2002-03043-1: CRCW040210K0FKEDHP; Manufacturer: Vishay Dale
R142 = CMP-1011-00718-3: RES Thick Film, 68.1kΩ, 1%, 0.063W, 100ppm/°C, 0402; Voltage Rating (DC): 50V; Max Power Dissipation: 63mW; Resistance: 68.1kR
R145 = CMP-009-00063-2: -55℃~+155℃ 100mW 135kΩ 75V Thin Film Resistor ±0.1% ±25ppm/℃ 0603 Chip Resistor - Surface Mount ROHS
R147 = CMP-2002-08356-2: RES Thick Film, 20kΩ, 1%, 0.063W, 100ppm/°C, 0402; Max Power Dissipation: 63mW; Working Voltage: 50V
R157 R186 = CMP-2002-00056-2: RES Thick Film, 4.87kΩ, 1%, 0.063W, 100ppm/°C, 0402 / CRCW04024K87FKED; Voltage Rating: 50V; Resistance: 4.87kR; Max Power Dissipation: 63mW
R158 = CMP-2000-03504-1: CRCW0603604RFKEA / Resistance = 604 Ω / Tolerance = 1.0% / Power = 100 mW; Manufacturer: Vishay Dale
R159 = CMP-2002-08161-1: Resistance = 11.5 kΩ / Tolerance = 1.0% / Power = 63 mW / CRCW040211K5FKED; Manufacturer: Vishay Dale
R160 R185 = CMP-2002-03043-1: 10KR / CRCW040210K0FKEDHP; Manufacturer: Vishay Dale
R184 = CMP-2000-04117-2: RES 6.04K OHM 1% 1/10W 0603 / RC0603FR-076K04L; Temperature Coefficient: 100ppm/°C; Voltage Rating: 50V; Power Rating: 100mW; Resistance: 6.04kR
R230 = CMP-2002-08208-2: RES Thick Film, 14.3kΩ, 1%, 0.063W, 100ppm/°C, 0402 / CRCW040214K3FKED; Voltage Rating (DC): 50V; Max Power Dissipation: 63mW; Resistance: 14.3kR
R334 = RSMT0215: Manufacturer 1: TE Connectivity; Manufacturer Part Number 1: 1622827-1; Tolerance: 1%; Description_: RES TKF 100k 1% 1/10W SMD 0603; Dev Tools Status: Production; Voltage: 75V; Power: 1/10W; Populated: YES; Owner: Cristian Papuc; Temperature Coefficient: 100ppm/C; Restricted Sourcing: No
R335 = RSMT1049: Manufacturer 1: Stackpole Electronics Inc; Manufacturer Part Number 1: RMCF0603FT15K0; Description_: RES TKF 15k 1% 1/10W SMD 0603; Dev Tools Status: Production; Voltage: 50V; Temperature Coeffcient: 100ppm/C; Current: 1A; Power: 1/10W; Owner: Leah Whitaker; Populated: Yes
R339 = RSMT1019: Manufacturer 1: Panasonic; Manufacturer Part Number 1: ERJ-2RKF1002X; Description_: RES TKF 10k 1% 1/10W SMD 0402; Dev Tools Status: Production; Temperature Coeffcient: 100ppm/C; Power: 1/10W; Populated: Yes; Voltage: 50V; Owner: Brent Lanphear
TP21 = CON1885: Test Point; Value: TP TH D1H0.6; Description_: CON TP PAD PCB TH D1H0.6; Dev Tools Status: Design; Owner: Gabor Bihari; Populated: DNP
U28 = TPS566242DRLR: -40℃~+125℃@(TJ) 1 120uA 3V~16V 600kHz 600mV~7V 6A Adjustable Buck Buck Built-in Yes SOT-563 DC-DC Converters ROHS
U34 = TPS566247DRLR: -40℃~+125℃@(TJ) 1 3V~16V 400uA 600kHz 600mV~7V 6A Adjustable Buck Buck Built-in Yes SOT-563 DC-DC Converters ROHS
U38 = MIC7045: Manufacturer 1: Microchip Technology; Manufacturer Part Number 1: MIC5377YC5-TR; Description_: MCHP ANALOG LDO 5.3V MIC5377YC5-TR SC70-5; Dev Tools Status: Production; Owner: Tim Moffat; Populated: YES
U39 U40 = PTPS62918RPYR: 17V VIN, 8A low-noise low-ripple buck converter with integrated ferrite-bead filter compensation 14-VQFN-HR -40 to 150; Manufacturer_Name: Texas Instruments

## Sheet 8841.SchDoc
size C; SheetNumber: 10; SheetTotal: 22
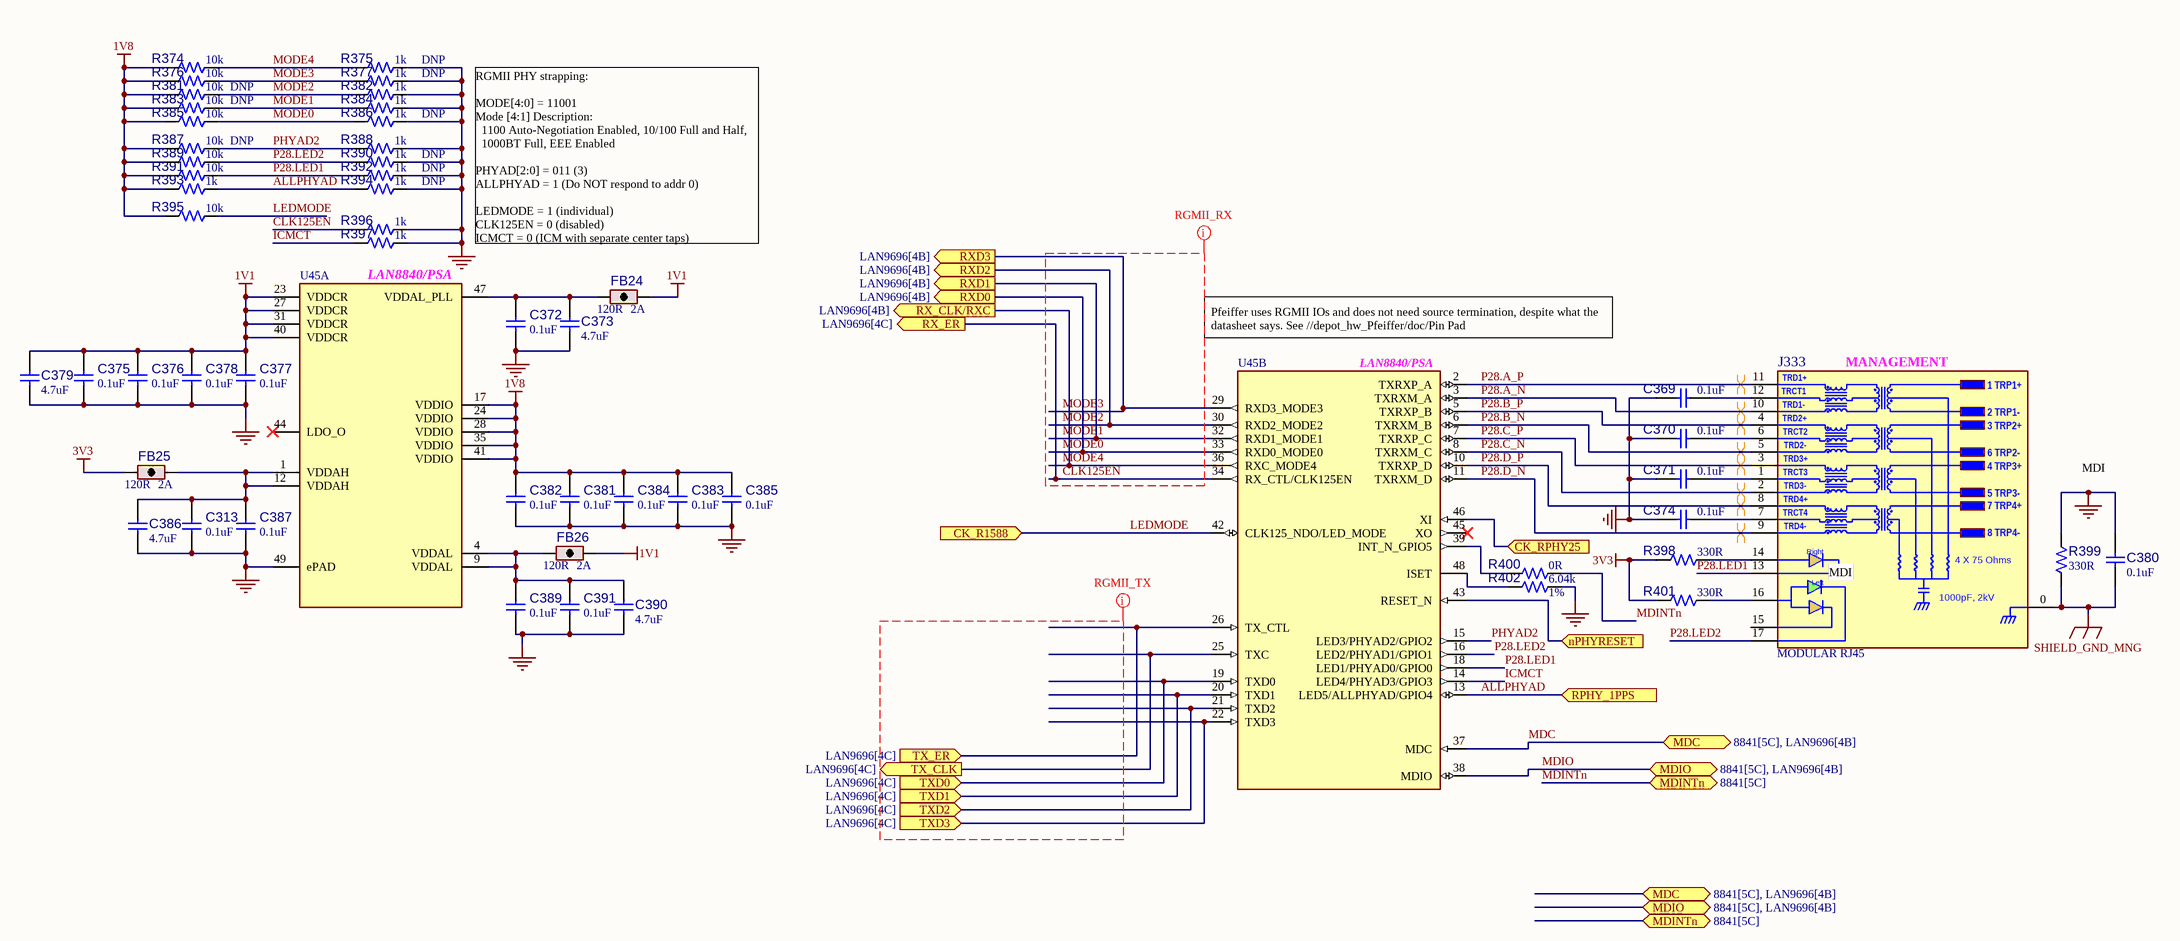
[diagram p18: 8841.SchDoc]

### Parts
C313  value 0.1uF  [CAP_C_0402]  (hidden comment: Capacitor NP)
C369  value 0.1uF  [CAP_C_0402]  (hidden comment: Capacitor NP)
C370  value 0.1uF  [CAP_C_0402]  (hidden comment: Capacitor NP)
C371  value 0.1uF  [CAP_C_0402]  (hidden comment: Capacitor NP)
C372  value 0.1uF  [CAP_C_0402]  (hidden comment: Capacitor NP)
C373  value 4.7uF  [CAP_C_0402]  (hidden comment: Capacitor NP)
C374  value 0.1uF  [CAP_C_0402]  (hidden comment: Capacitor NP)
C375  value 0.1uF  [CAP_C_0402]  (hidden comment: Capacitor NP)
C376  value 0.1uF  [CAP_C_0402]  (hidden comment: Capacitor NP)
C377  value 0.1uF  [CAP_C_0402]  (hidden comment: Capacitor NP)
C378  value 0.1uF  [CAP_C_0402]  (hidden comment: Capacitor NP)
C379  value 4.7uF  [CAP_C_0402]  (hidden comment: Capacitor NP)
C380  value 0.1uF  [CAP_C_0402]  (hidden comment: Capacitor NP)
C381  value 0.1uF  [CAP_C_0402]  (hidden comment: Capacitor NP)
C382  value 0.1uF  [CAP_C_0402]  (hidden comment: Capacitor NP)
C383  value 0.1uF  [CAP_C_0402]  (hidden comment: Capacitor NP)
C384  value 0.1uF  [CAP_C_0402]  (hidden comment: Capacitor NP)
C385  value 0.1uF  [CAP_C_0402]  (hidden comment: Capacitor NP)
C386  value 4.7uF  [CAP_C_0402]  (hidden comment: Capacitor NP)
C387  value 0.1uF  [CAP_C_0402]  (hidden comment: Capacitor NP)
C389  value 0.1uF  [CAP_C_0402]  (hidden comment: Capacitor NP)
C390  value 4.7uF  [CAP_C_0402]  (hidden comment: Capacitor NP)
C391  value 0.1uF  [CAP_C_0402]  (hidden comment: Capacitor NP)
FB24  value 120R  RMS Current: 2A  [IND_C_0603]  (hidden comment: Ferrite Bead)
FB25  value 120R  RMS Current: 2A  [IND_C_0603]  (hidden comment: Ferrite Bead)
FB26  value 120R  RMS Current: 2A  [IND_C_0603]  (hidden comment: Ferrite Bead)
J333  value MODULAR RJ45  Legend Note: MANAGEMENT  [CON_JACK_RJ45_L829-1J1T-43]  (hidden comment: CON_RJ-45_L829-1J1T-43)
R374  value 10k  [RES_C_0402]  (hidden comment: Resistor)
R375  value 1k  Populated: DNP  [RES_C_0402]  (hidden comment: Resistor)
R376  value 10k  [RES_C_0402]  (hidden comment: Resistor)
R377  value 1k  Populated: DNP  [RES_C_0402]  (hidden comment: Resistor)
R381  value 10k  Populated: DNP  [RES_C_0402]  (hidden comment: Resistor)
R382  value 1k  [RES_C_0402]  (hidden comment: Resistor)
R383  value 10k  Populated: DNP  [RES_C_0402]  (hidden comment: Resistor)
R384  value 1k  [RES_C_0402]  (hidden comment: Resistor)
R385  value 10k  [RES_C_0402]  (hidden comment: Resistor)
R386  value 1k  Populated: DNP  [RES_C_0402]  (hidden comment: Resistor)
R387  value 10k  Populated: DNP  [RES_C_0402]  (hidden comment: Resistor)
R388  value 1k  [RES_C_0402]  (hidden comment: Resistor)
R389  value 10k  [RES_C_0402]  (hidden comment: Resistor)
R390  value 1k  Populated: DNP  [RES_C_0402]  (hidden comment: Resistor)
R391  value 10k  [RES_C_0402]  (hidden comment: Resistor)
R392  value 1k  Populated: DNP  [RES_C_0402]  (hidden comment: Resistor)
R393  value 1k  [RES_C_0402]  (hidden comment: Resistor)
R394  value 1k  Populated: DNP  [RES_C_0402]  (hidden comment: Resistor)
R395  value 10k  [RES_C_0402]  (hidden comment: Resistor)
R396  value 1k  [RES_C_0402]  (hidden comment: Resistor)
R397  value 1k  [RES_C_0402]  (hidden comment: Resistor)
R398  value 330R  [RES_C_0402]  (hidden comment: Resistor)
R399  value 330R  [RES_C_0402]  (hidden comment: Resistor)
R400  value 0R  [RES_C_0402]  (hidden comment: Resistor)
R401  value 330R  [RES_C_0402]  (hidden comment: Resistor)
R402  value 6.04k  Tolerance: 1%  [RES_C_0402]  (hidden comment: Resistor)
U45  Legend Note: LAN8840/PSA  [QFN-48_7x7_EP5.1x5.1]  (hidden comment: LAN8840_QFN-48_TEST)  (parts A,B of 2)

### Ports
CK_R1588 (in), CK_RPHY25 (in), MDC (bidir, see 8841[5C], LAN9696[4B]), MDINTn (bidir, see 8841[5C]), MDIO (bidir, see 8841[5C], LAN9696[4B]), nPHYRESET (in), RPHY_1PPS (in), RX_CLK/RXC (out, see LAN9696[4B]), RX_ER (out, see LAN9696[4C]), RXD0 (out, see LAN9696[4B]), RXD1 (out, see LAN9696[4B]), RXD2 (out, see LAN9696[4B]), RXD3 (out, see LAN9696[4B]), TX_CLK (out, see LAN9696[4C]), TX_ER (in, see LAN9696[4C]), TXD0 (in, see LAN9696[4C]), TXD1 (in, see LAN9696[4C]), TXD2 (in, see LAN9696[4C]), TXD3 (in, see LAN9696[4C])

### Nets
1V1: C375.1 C376.1 C377.1 C378.1 C379.1 FB24.2 FB26.2 U45.23(VDDCR) U45.27(VDDCR) U45.31(VDDCR) U45.40(VDDCR)
1V8: C381.1 C382.1 C383.1 C384.1 C385.1 R374.2 R376.2 R381.2 R383.2 R385.2 R387.2 R389.2 R391.2 R393.2 R395.2 U45.17(VDDIO) U45.24(VDDIO) U45.28(VDDIO) U45.35(VDDIO) U45.41(VDDIO)
3V3: FB25.1 R398.2 R401.2
GND: C313.2 C369.2 C370.2 C371.2 C372.2 C373.2 C374.2 C375.2 C376.2 C377.2 C378.2 C379.2 C380.2 C381.2 C382.2 C383.2 C384.2 C385.2 C386.2 C387.2 C389.2 C390.2 C391.2 R375.1 R377.1 R382.1 R384.1 R386.1 R388.1 R390.1 R392.1 R394.1 R396.1 R397.1 R399.2 R402.1 U45.49(ePAD)
SHIELD_GND_MNG: C380.1 J333.0(SHLD) R399.1
ALLPHYAD: R393.1 R394.2 U45.13(LED5/ALLPHYAD/GPIO4) ; port RPHY_1PPS
CK_RPHY25: U45.46(XI) ; port CK_RPHY25
CLK125EN: R396.2 U45.34(RX_CTL/CLK125EN) ; port RX_ER
ICMCT: R397.2 U45.14(LED4/PHYAD3/GPIO3)
LEDMODE: R395.1 U45.42(CLK125_NDO/LED_MODE) ; port CK_R1588
MDC: U45.37(MDC) ; port MDC
MDINTn: R400.2 ; port MDINTn
MDIO: U45.38(MDIO) ; port MDIO
MODE0: R385.1 R386.2 U45.33(RXD0_MODE0) ; port RXD0
MODE1: R383.1 R384.2 U45.32(RXD1_MODE1) ; port RXD1
MODE2: R381.1 R382.2 U45.30(RXD2_MODE2) ; port RXD2
MODE3: R376.1 R377.2 U45.29(RXD3_MODE3) ; port RXD3
MODE4: R374.1 R375.2 U45.36(RXC_MODE4) ; port RX_CLK/RXC
nPHYRESET: U45.43(RESET_N) ; port nPHYRESET
P28.A_N: J333.10 U45.3(TXRXM_A)
P28.A_P: J333.11 U45.2(TXRXP_A)
P28.B_N: J333.5 U45.6(TXRXM_B)
P28.B_P: J333.4 U45.5(TXRXP_B)
P28.C_N: J333.2 U45.8(TXRXM_C)
P28.C_P: J333.3 U45.7(TXRXP_C)
P28.D_N: J333.9 U45.11(TXRXM_D)
P28.D_P: J333.8 U45.10(TXRXP_D)
P28.LED1: J333.13 R391.1 R392.2 U45.18(LED1/PHYAD0/GPIO0)
P28.LED2: J333.17 R389.1 R390.2 U45.16(LED2/PHYAD1/GPIO1)
PHYAD2: R387.1 R388.2 U45.15(LED3/PHYAD2/GPIO2)
TX_CLK: U45.25(TXC) ; port TX_CLK
TX_ER: U45.26(TX_CTL) ; port TX_ER
TXD0: U45.19(TXD0) ; port TXD0
TXD1: U45.20(TXD1) ; port TXD1
TXD2: U45.21(TXD2) ; port TXD2
TXD3: U45.22(TXD3) ; port TXD3
NetC313_1: C313.1 C386.1 C387.1 FB25.2 U45.1(VDDAH) U45.12(VDDAH)
NetC369_1: C369.1 J333.12
NetC370_1: C370.1 J333.6
NetC371_1: C371.1 J333.1
NetC372_1: C372.1 C373.1 FB24.1 U45.47(VDDAL_PLL)
NetC374_1: C374.1 J333.7
NetC389_1: C389.1 C390.1 C391.1 FB26.1 U45.4(VDDAL) U45.9(VDDAL)
NetJ333_14: J333.14 R398.1
NetJ333_16: J333.16 R401.1
NetR400_1: R400.1 U45.39(INT_N_GPIO5)
NetR402_2: R402.2 U45.48(ISET)

Not connected (* = marked no-connect by the designer): J333 15; U45 44(LDO_O)* 45(XO)*

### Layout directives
differential pair; net class MDI; rule Impedance Constraint [Min = 95.00    Max = 105.0    ]; rule Maximum Via Count Constraint [Max Count = 1]; rule Matched Net Lengths [Tolerance = 40mil]; differential pair class MDI: P28.A_N, P28.A_P, P28.B_N, P28.B_P, P28.C_N, P28.C_P, P28.D_N, P28.D_P
rule Impedance Constraint [Min = 47.00    Max = 53.00    ]; net class RGMII_RX; rule Routing Topology [Topology - Daisy-Simple]; rule Matched Net Lengths [Tolerance = 100mil]: CLK125EN, MODE0, MODE1, MODE2, MODE3, MODE4
rule Impedance Constraint [Min = 47.00    Max = 53.00    ]; net class RGMII_TX; rule Routing Topology [Topology - Daisy-Simple]; rule Matched Net Lengths [Tolerance = 100mil]: (no net found under the mark)

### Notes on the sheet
- RGMII PHY strapping:
  MODE[4:0] = 11001
  Mode [4:1] Description:
  1100 Auto-Negotiation Enabled, 10/100 Full and Half,
  1000BT Full, EEE Enabled
  PHYAD[2:0] = 011 (3)
  ALLPHYAD = 1 (Do NOT respond to addr 0)
  LEDMODE = 1 (individual)
  CLK125EN = 0 (disabled)
  ICMCT = 0 (ICM with separate center taps)
- (near U45) Pfeiffer uses RGMII IOs and does not need source termination, despite what the datasheet says. See //depot_hw_Pfeiffer/doc/Pin Pad Map/B0/Pfeiffer_B0_48_64_88_041422.xls
- MDI
- (near J333) MDI

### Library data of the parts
C313 C369-C372 C374-C378 C380-C385 C387 C389 C391 = CAP1463: Manufacturer 1: TDK Corporation; Manufacturer Part Number 1: C1005X7R1H104K050BB; Voltage: 50V; Description_: CAP CER 0.1uF 50V 10% X7R SMD 0402; Dev Tools Status: Production; Tolerance: 10%; Type: Ceramic; Owner: Jamus Griego; Populated: YES; Temperature Coefficient: X7R; Restricted Sourcing: No
C373 C379 C386 C390 = CAP1207: Manufacturer 1: Murata; Manufacturer Part Number 1: GRM155R60J475ME47D; Voltage: 6.3V; Description_: CAP CER 4.7uF 6.3V 20% X5R SMD 0402; Dev Tools Status: Production; Tolerance: 20%; Temperature Coeffcient: X5R; Type: Ceramic; Populated: YES; Owner: Tad Ahlvers; Restricted Sourcing: No
FB24-FB26 = IND1640: as FB1 on sheet LAN9696_Supply
J333 = CON2551: Manufacturer 1: Bel Fuse; Description_: CON MODULAR JACK RJ45 10/100/1000 MAGNETICS 2xLEDs SHIELD TH; Dev Tools Status: Design; Owner: Sam Charles; Populated: YES; Restricted Sourcing: No
R374 R376 R385 R389 R391 R395 = RSMT1019: as R1 on sheet LAN9696
R375 R377 R386 R390 R392 R394 = RES1022: Manufacturer 1: Panasonic; Manufacturer Part Number 1: ERJ-2RKF1001X; Tolerance: 1%; Description_: RES TKF 1k 1% 1/10W SMD 0402; Dev Tools Status: Production; Voltage: 50V; Power: 1/10W; Owner: Tad Ahlvers; Temperature Coefficient: 100ppm/C
R381 R383 R387 = RSMT1019: as R6 on sheet LAN9696
R382 R384 R388 R396 R397 = RES1022: as R10 on sheet LAN9696
R393 = RES1022: Manufacturer 1: Panasonic; Manufacturer Part Number 1: ERJ-2RKF1001X; Tolerance: 1%; Description_: RES TKF 1k 1% 1/10W SMD 0402; Dev Tools Status: Production; Power: 1/10W; Populated: YES; Voltage: 50V; Owner: Tad Ahlvers; Temperature Coefficient: 100ppm/C
R398 R401 = RSMT1100: Manufacturer 1: Yageo; Manufacturer Part Number 1: RC0402FR-07330RL; Tolerance: 1%; Description_: RES TKF 330R 1% 1/16W SMD 0402; Dev Tools Status: Production; Power: 1/16W; Populated: YES; Owner: Mike Ragsdale; Circuit Type: Isolated; Restricted Sourcing: No
R399 = RSMT1100: Manufacturer 1: Yageo; Manufacturer Part Number 1: RC0402FR-07330RL; Tolerance: 1%; Description_: RES TKF 330R 1% 1/16W SMD 0402; Dev Tools Status: Production; Power: 1/16W; Populated: YES; Circuit Type: Isolated; Owner: Mike Ragsdale; Restricted Sourcing: No
R400 = RSMT1040: as R11 on sheet LAN9696
R402 = RES2380: Manufacturer 1: Panasonic Electronic Components; Manufacturer Part Number 1: ERJ-2RKF6041X; Description_: RES TKF 6.04k 1% 1/10W SMD 0402 AEC-Q200; Dev Tools Status: Production; Circuit Type: Isolated; Power: 1/10W; Owner: Steve Dziaba; Populated: YES; Restricted Sourcing: No
U45 = MIC8558: Manufacturer 1: Microchip Technology; Description_: MCHP INTERFACE ETHERNET LAN8840 QFN-48; Dev Tools Status: Design; Owner: Sam Charles; Populated: YES; Restricted Sourcing: No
